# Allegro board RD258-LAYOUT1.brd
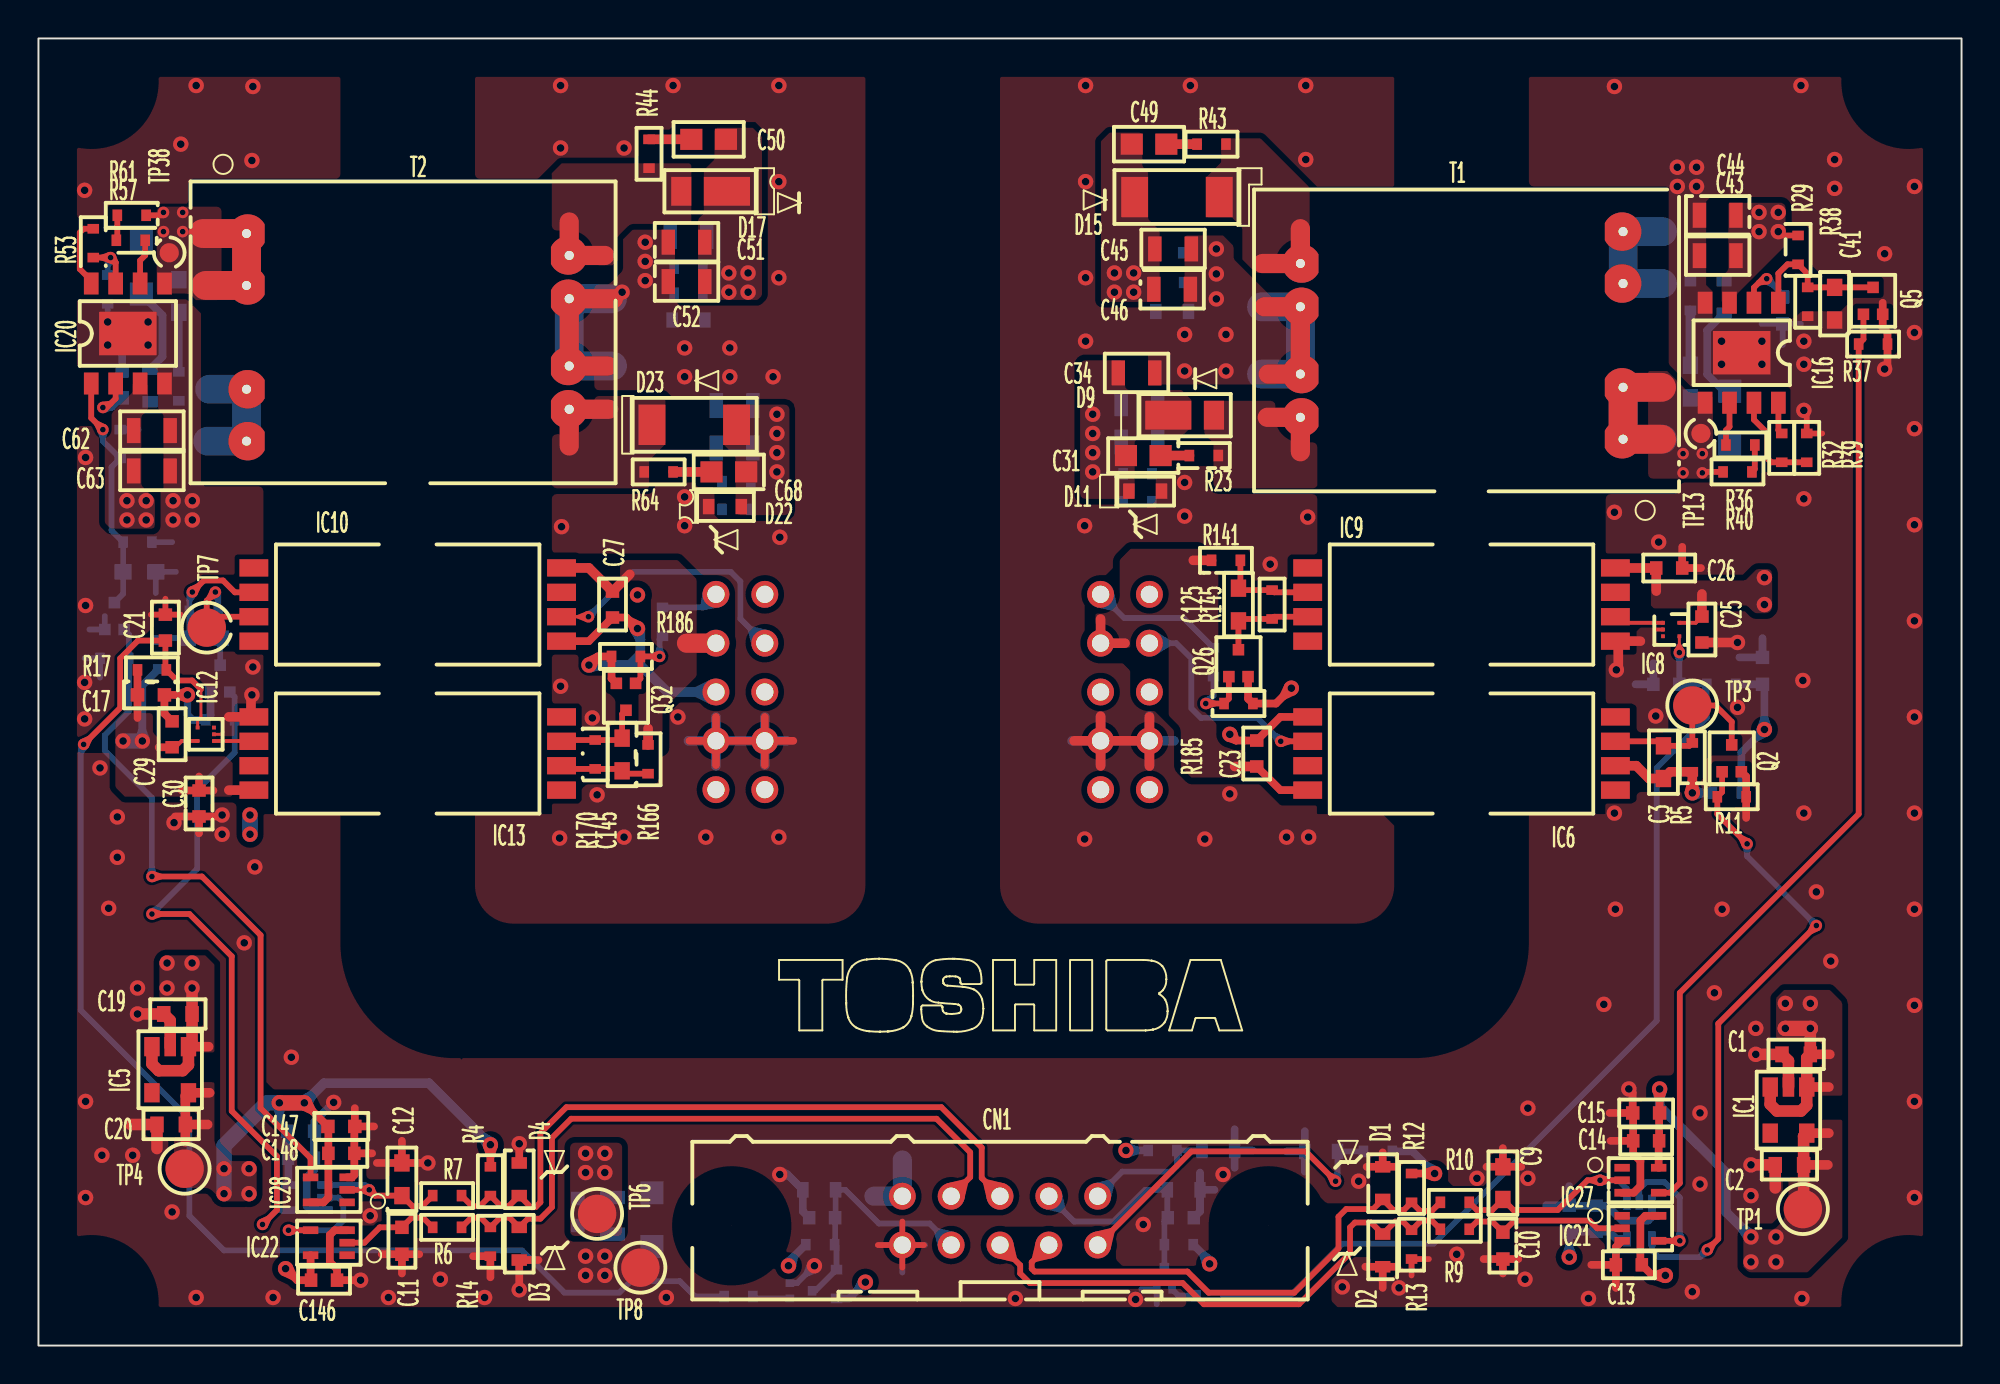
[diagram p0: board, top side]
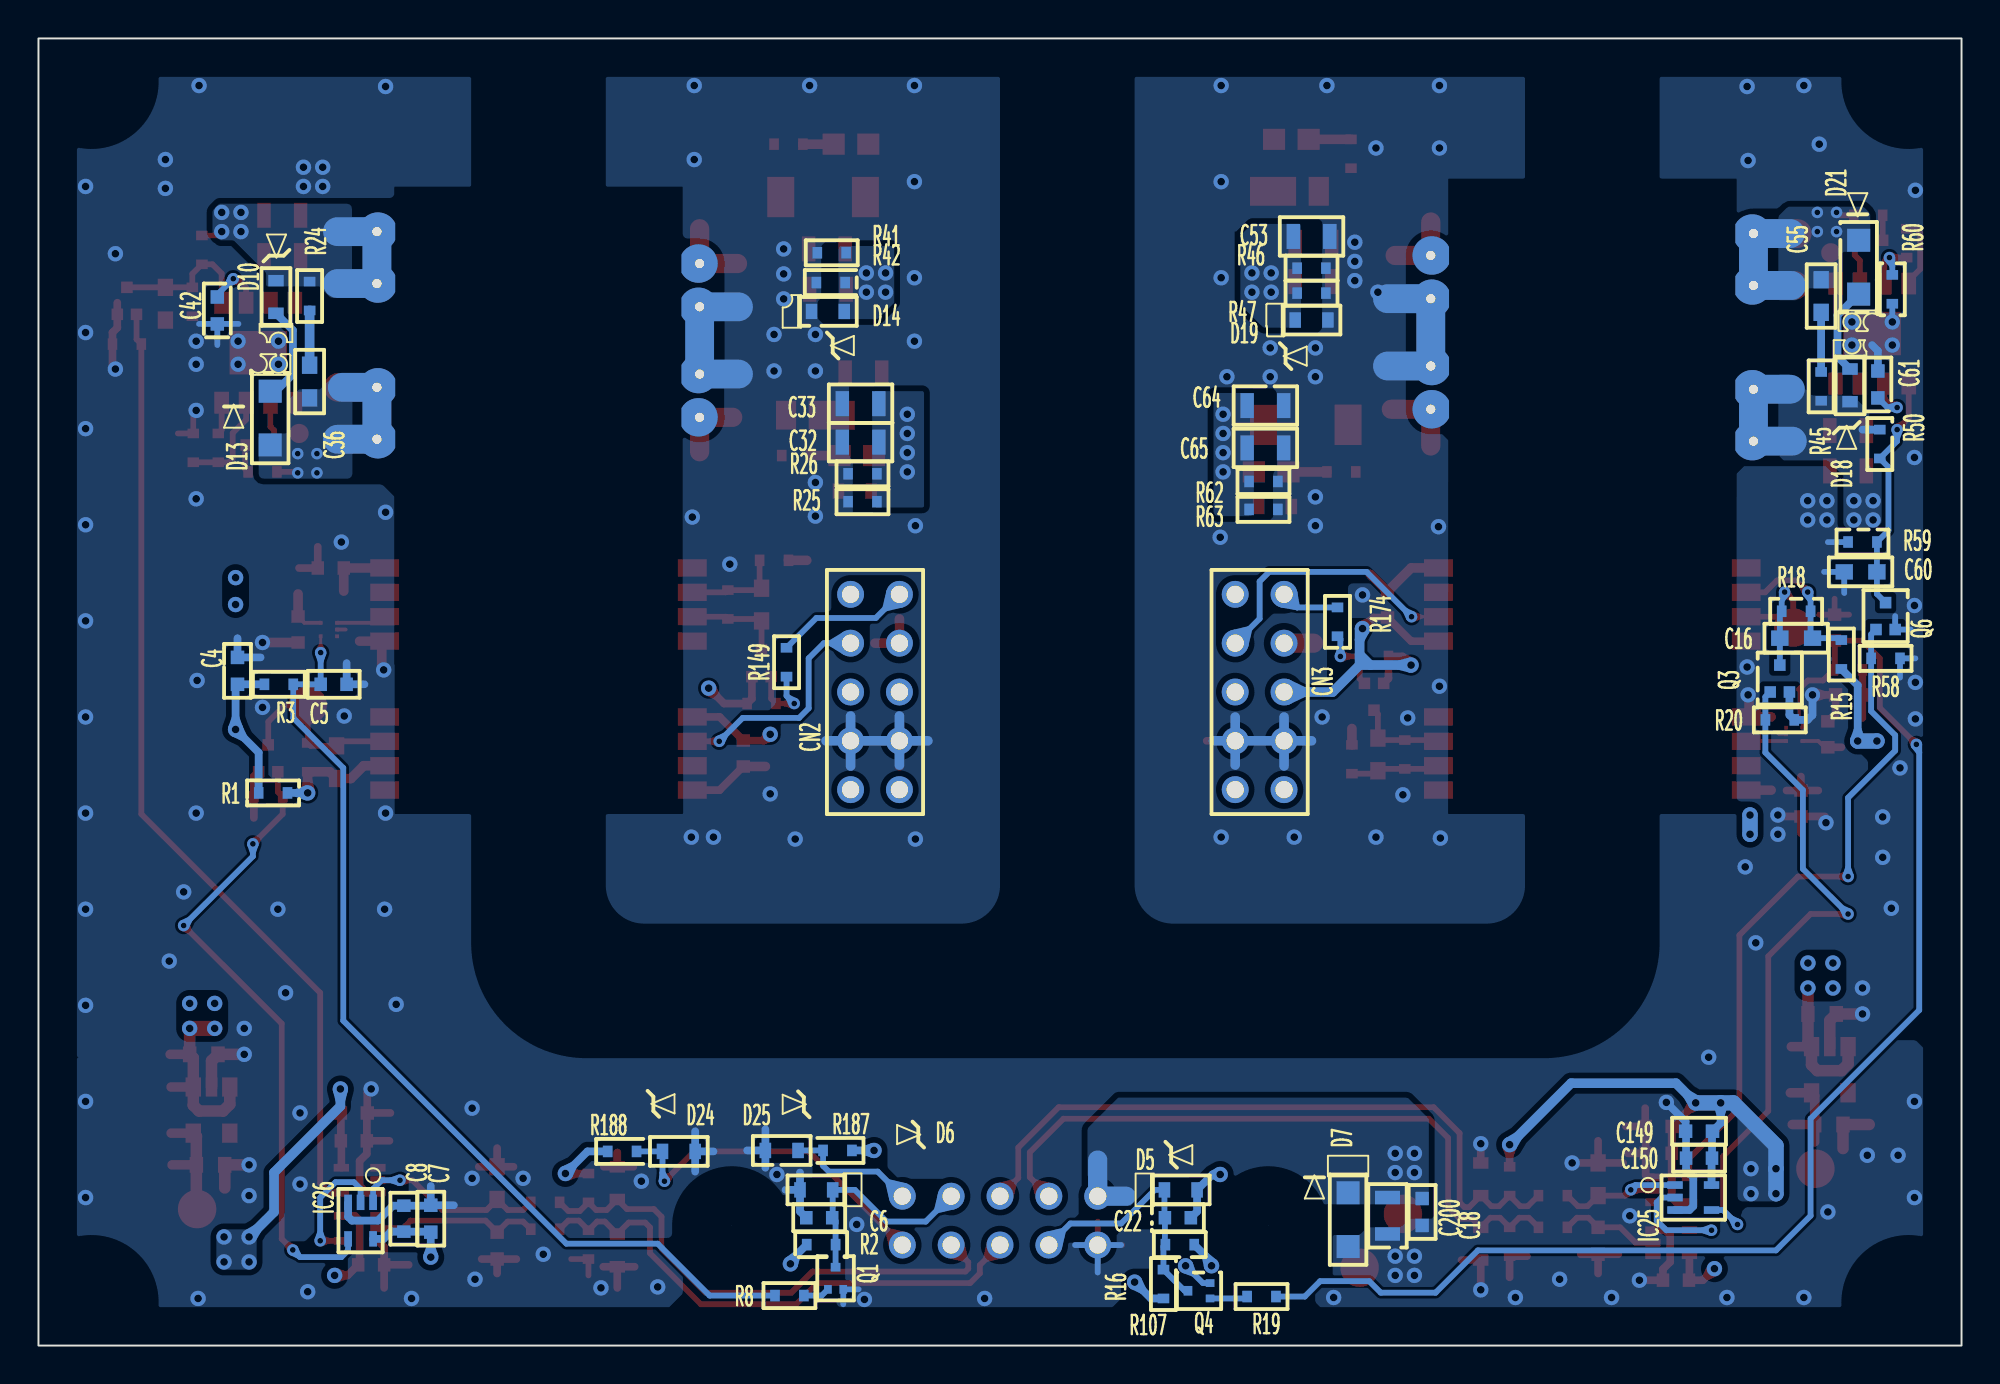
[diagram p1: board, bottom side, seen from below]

Outline 100 x 68 mm; copper layers: TOP, CONDUCTIVE2, CONDUCTIVE3, BOTTOM. Coordinates in mm from the lower left corner of the outline.
Outline path: rectangle 0,0 100,68

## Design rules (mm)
constraint set DEFAULT: 

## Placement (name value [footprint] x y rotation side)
C1  -  [C_CHP_TYYDN_L1_6W0_8H0_8A]  91.4 15.15 0 top
C2  -  [C_CHP_TYYDN_L1_6W0_8H0_8A]  91.05 9.4 0 top
C3  -  [C_CHP_YAGEO_L1_6W0_8H0_8]  84.5 30.35 270 top
C4  -  [C_CHP_TDK_L1_6W0_8H0_8]  89.65 35.1 270 bottom
C5  -  [C_CHP_MURATA_L1_6W0_8H0_8A]  84.65 34.4 0 bottom
C6  -  [C_CHP_MURATA_L1_6W0_8H0_8A]  59.4 6.65 180 bottom
C7  -  [C_CHP_TDK_L1_6W0_8H0_8]  79.6 6.6 270 bottom
C8  -  [C_CHP_MURATA_L1_6W0_8H0_8A]  81 6.6 270 bottom
C9  -  [C_CHP_YAGEO_L1_6W0_8H0_8]  76.15 8.45 270 top
C10  -  [C_CHP_TDK_L1_6W0_8H0_8]  76.15 5.2 90 top
C11  -  [C_CHP_TDK_L1_6W0_8H0_8]  18.9 5.45 90 top
C12  -  [C_CHP_YAGEO_L1_6W0_8H0_8]  18.9 8.65 270 top
C13  -  [C_CHP_MURATA_L1_6W0_8H0_8A]  82.7 4.2 0 top
C14  -  [C_CHP_MURATA_L1_6W0_8H0_8A]  83.6 10.65 0 top
C15  -  [C_CHP_TDK_L1_6W0_8H0_8]  83.6 12.1 0 top
C16  -  [C_CHP_YAGEO_L1_6W0_8H0_8]  8.6 36.8 180 bottom
C17  -  [C_CHP_TDK_L1_6W0_8H0_8]  5.85 33.85 180 top
C18  -  [C_CHP_TDK_L1_6W0_8H0_8]  28.05 6.95 90 bottom
C19  -  [C_CHP_TYYDN_L1_6W0_8H0_8A]  7.25 17.25 0 top
C20  -  [C_CHP_TYYDN_L1_6W0_8H0_8A]  6.9 11.5 0 top
C21  -  [C_CHP_MURATA_L1_6W0_8H0_8A]  6.6 37.35 270 top
C22  -  [C_CHP_MURATA_L1_6W0_8H0_8A]  40.75 6.65 0 bottom
C23  -  [C_CHP_MURATA_L1_6W0_8H0_8A]  63.35 30.8 270 top
C25  -  [C_CHP_MURATA_L1_6W0_8H0_8A]  86.5 37.25 90 top
C26  -  [C_CHP_MURATA_L1_6W0_8H0_8A]  84.8 40.45 180 top
C27  -  [C_CHP_MURATA_L1_6W0_8H0_8A]  29.85 38.55 90 top
C29  -  [C_CHP_MURATA_L1_6W0_8H0_8A]  6.95 31.8 270 top
C30  -  [C_CHP_MURATA_L1_6W0_8H0_8A]  8.35 28.2 90 top
C31  -  [C_CHP_KEMET_L1_6W0_8H0_8]  57.45 46.3 0 top
C32  -  [C_CHP_MURATA_L2_0W1_25H1_25]  57.25 47 180 bottom
C33  -  [C_CHP_MURATA_L2_0W1_25H1_25]  57.25 49 180 bottom
C34  -  [C_CHP_MURATA_L2_0W1_25H1_25]  57.1 50.6 180 top
C36  -  [C_CHP_YAGEO_L1_6W0_8H0_8]  85.9 50.15 90 bottom
C41  -  [C_CHP_YAGEO_L1_6W0_8H0_8]  93.4 54.2 90 top
C42  -  [C_CHP_TDK_L1_6W0_8H0_8]  90.7 53.85 90 bottom
C43  -  [C_CHP_MURATA_L2_0W1_25H1_25]  87.32 56.7 0 top
C44  -  [C_CHP_MURATA_L2_0W1_25H1_25]  87.32 58.8 0 top
C45  -  [C_CHP_MURATA_L2_0W1_25H1_25]  59 57.05 0 top
C46  -  [C_CHP_MURATA_L2_0W1_25H1_25]  58.95 54.95 0 top
C49  -  [C_CHP_KEMET_L1_6W0_8H0_8]  57.75 62.5 0 top
C50  -  [C_CHP_KEMET_L1_6W0_8H0_8]  34.85 62.75 180 top
C51  -  [C_CHP_MURATA_L2_0W1_25H1_25]  33.7 57.4 0 top
C52  -  [C_CHP_MURATA_L2_0W1_25H1_25]  33.7 55.35 0 top
C53  -  [C_CHP_MURATA_L2_0W1_25H1_25]  33.8 57.7 0 bottom
C55  -  [C_CHP_YAGEO_L1_6W0_8H0_8]  7.3 54.6 270 bottom
C60  -  [C_CHP_YAGEO_L1_6W0_8H0_8]  5.25 40.25 180 bottom
C61  -  [C_CHP_TDK_L1_6W0_8H0_8]  4.35 50 270 bottom
C62  -  [C_CHP_MURATA_L2_0W1_25H1_25]  5.9 47.6 180 top
C63  -  [C_CHP_MURATA_L2_0W1_25H1_25]  5.9 45.5 180 top
C64  -  [C_CHP_MURATA_L2_0W1_25H1_25]  36.2 48.9 180 bottom
C65  -  [C_CHP_MURATA_L2_0W1_25H1_25]  36.2 46.7 180 bottom
C68  -  [C_CHP_KEMET_L1_6W0_8H0_8]  35.9 45.45 180 top
C125  -  [C_CHP_YAGEO_L1_6W0_8H0_8]  62.4 38.55 90 top
C145  -  [C_CHP_YAGEO_L1_6W0_8H0_8]  30.35 30.75 270 top
C146  -  [C_CHP_MURATA_L1_6W0_8H0_8A]  14.85 3.4 0 top
C147  -  [C_CHP_TDK_L1_6W0_8H0_8]  15.75 11.4 180 top
C148  -  [C_CHP_MURATA_L1_6W0_8H0_8A]  15.75 10 180 top
C149  -  [C_CHP_TDK_L1_6W0_8H0_8]  13.65 11.15 180 bottom
C150  -  [C_CHP_MURATA_L1_6W0_8H0_8A]  13.65 9.75 180 bottom
C200  -  [C_CHP_MURATA_L2_0W1_25H1_25]  29.85 6.75 90 bottom
CN1  -  [CN_IMD_OMRON_XG4A_1031_M1_M2]  44.92 5.23 0 top
CN2  -  [OWW_3_15_5PW]  55.23 28.92 90 bottom
CN3  -  [OWW_3_15_5PW]  35.23 28.92 90 bottom
D1  -  [ZD_SMD_TSB_K_1_A_2_L1_2W0_8H0_6]  69.9 8.45 90 top
D2  -  [ZD_SMD_TSB_K_1_A_2_L1_2W0_8H0_6]  69.9 4.95 270 top
D3  -  [ZD_SMD_TSB_K_1_A_2_L1_2W0_8H0_6]  25 5.3 270 top
D4  -  [ZD_SMD_TSB_K_1_A_2_L1_2W0_8H0_6]  25 8.65 90 top
D5  -  [ZD_SMD_TSB_K_1_A_2_L1_2W0_8H0_6]  40.6 8.1 180 bottom
D6  -  [ZD_SMD_TSB_K_1_A_2_L1_2W0_8H0_6]  59.55 8.1 0 bottom
D7  -  [D_SMD_TSB_K_2_A_1_L2_6W1_6H0_98]  31.9 6.55 270 bottom
D9  -  [D_SMD_DIODES_K_C_A_A_L2_8W1_78H0_98]  59.6 48.4 0 top
D10  -  [ZD_SMD_TSB_K_1_A_2_L1_2W0_8H0_6]  87.65 54.55 90 bottom
D11  -  [ZD_SMD_TSB_K_1_A_2_L1_2W0_8H0_6]  57.55 44.45 0 top
D13  -  [D_SMD_TSB_K_2_A_1_L2_6W1_6H0_98]  87.95 48.25 270 bottom
D14  -  [ZD_SMD_TSB_K_1_A_2_L1_2W0_8H0_6]  58.95 53.8 180 bottom
D15  -  [D_SMD_TSB_K_2_A_1_L3_8W2_4H0_98]  59.2 59.75 180 top
D17  -  [D_SMD_DIODES_K_C_A_A_L2_8W1_78H0_98]  34.95 60.05 180 top
D18  -  [ZD_SMD_TSB_K_1_A_2_L1_2W0_8H0_6]  5.8 49.95 270 bottom
D19  -  [ZD_SMD_TSB_K_1_A_2_L1_2W0_8H0_6]  33.8 53.35 180 bottom
D21  -  [D_SMD_TSB_K_2_A_1_L2_6W1_6H0_98]  5.35 56.1 90 bottom
D22  -  [ZD_SMD_TSB_K_1_A_2_L1_2W0_8H0_6]  35.7 43.65 0 top
D23  -  [D_SMD_TSB_K_2_A_1_L3_8W2_4H0_98]  34.1 47.9 0 top
D24  -  [ZD_SMD_TSB_K_1_A_2_L1_2W0_8H0_6]  66.7 10.1 180 bottom
D25  -  [ZD_SMD_TSB_K_1_A_2_L1_2W0_8H0_6]  61.35 10.15 0 bottom
IC1  -  [IC_SC74A_TSB_L2_9W1_6H1_15_RP0_05]  91 12.25 180 top
IC5  -  [IC_SC74A_TSB_L2_9W1_6H1_15_RP0_05]  6.85 14.35 180 top
IC6  -  [PC_SOP_8_TSB_L6_25W13_75H3_7_P1_27_3]  74 30.8 90 top
IC8  -  [IC_SMD_5_TSB_L1_0W0_8H0_48_RCNT]  84.9 37.25 270 top
IC9  -  [PC_SOP_8_TSB_L6_25W13_75H3_7_P1_27_3]  74 38.55 270 top
IC10  -  [PC_SOP_8_TSB_L6_25W13_75H3_7_P1_27_3]  19.2 38.55 270 top
IC12  -  [IC_SMD_5_TSB_L1_0W0_8H0_48_RCNT]  8.7 31.8 90 top
IC13  -  [PC_SOP_8_TSB_L6_25W13_75H3_7_P1_27_3]  19.2 30.8 90 top
IC16  -  [IC_SOP_8S1_AD_L5_004W3_988H1_752_P1_27_2]  88.57 51.65 180 top
IC20  -  [IC_SOP_8S1_AD_L5_004W3_988H1_752_P1_27_2]  4.65 52.65 0 top
IC21  -  [IC_SOP_5_TSB_L2_0W1_25H0_95_RP0_05]  83.3 6.1 270 top
IC22  -  [IC_SOP_5_TSB_L2_0W1_25H0_95_RP0_05]  15.1 5.35 90 top
IC25  -  [IC_SOP_5_TSB_L2_0W1_25H0_95_RP0_05]  13.95 7.7 270 bottom
IC26  -  [IC_SOP_5_TSB_L2_0W1_25H0_95_RP0_05]  83.25 6.5 0 bottom
IC27  -  [IC_SOP_5_TSB_L2_0W1_25H0_95_RP0_05]  83.3 8.6 270 top
IC28  -  [IC_SOP_5_TSB_L2_0W1_25H0_95_RP0_05]  15.1 8.1 90 top
NOREF  -  []  38.5 16.4 0 top
Q1  -  [TR_SMD_3_TSB_B_1_E_2_C_3_L1_2W0_8H0_5]  58.55 3.5 180 bottom
Q2  -  [FET_SMD_TSB_G_1_S_2_D_3_L1_6W0_8H0_75]  88.05 30.55 0 top
Q3  -  [FET_SMD_TSB_G_1_S_2_D_3_L1_6W0_8H0_75]  9.45 34.7 180 bottom
Q4  -  [TR_SMD_3_TSB_B_1_E_2_C_3_L1_2W0_8H0_5]  39.65 2.85 90 bottom
Q5  -  [FET_SMD_TSB_G_1_S_2_D_3_L1_6W0_8H0_75]  95.4 54.35 0 top
Q6  -  [FET_SMD_TSB_G_1_S_2_D_3_L1_6W0_8H0_75]  3.95 37.95 180 bottom
Q26  -  [FET_SMD_TSB_G_1_S_2_D_3_L1_6W0_8H0_75]  62.4 35.5 0 top
Q32  -  [FET_SMD_TSB_G_1_S_2_D_3_L1_6W0_8H0_75]  30.55 33.75 180 top
R1  -  [R_CHP_KOA_L1_6W0_8H0_45]  87.8 28.75 0 bottom
R2  -  [R_CHP_KOA_L1_6W0_8H0_45]  59.3 5.25 0 bottom
R3  -  [R_CHP_KOA_L1_6W0_8H0_45]  87.5 34.4 0 bottom
R4  -  [R_CHP_KOA_L1_6W0_8H0_45]  23.5 8.55 90 top
R5  -  [R_CHP_KOA_L1_6W0_8H0_45]  86 30.6 270 top
R6  -  [R_CHP_KOA_L1_6W0_8H0_45]  21.25 6.15 180 top
R7  -  [R_CHP_KOA_L1_6W0_8H0_45]  21.25 7.8 180 top
R8  -  [R_CHP_KOA_L1_6W0_8H0_45]  60.95 2.6 0 bottom
R9  -  [R_CHP_KOA_L1_6W0_8H0_45]  73.65 6.05 0 top
R10  -  [R_CHP_KOA_L1_6W0_8H0_45]  73.65 7.45 0 top
R11  -  [R_CHP_KOA_L1_6W0_8H0_45]  88.05 28.55 180 top
R12  -  [R_CHP_KOA_L1_6W0_8H0_45]  71.4 8.2 90 top
R13  -  [R_CHP_KOA_L1_6W0_8H0_45]  71.4 5.25 90 top
R14  -  [R_CHP_KOA_L1_6W0_8H0_45]  23.5 5.4 90 top
R15  -  [R_CHP_KOA_L1_6W0_8H0_45]  6.25 35.95 270 bottom
R16  -  [R_CHP_KOA_L1_6W0_8H0_45]  40.65 5.25 180 bottom
R17  -  [R_CHP_KOA_L1_6W0_8H0_45]  5.9 35.15 180 top
R18  -  [R_CHP_KOA_L1_6W0_8H0_45]  8.6 38.2 180 bottom
R19  -  [R_CHP_KOA_L1_6W0_8H0_45]  36.4 2.55 180 bottom
R20  -  [R_CHP_KOA_L1_6W0_8H0_45]  9.45 32.55 0 bottom
R23  -  [R_CHP_KOA_L1_6W0_8H0_45]  60.6 46.3 0 top
R24  -  [R_CHP_KOA_L1_6W0_8H0_45]  85.9 54.6 90 bottom
R25  -  [R_CHP_KOA_L1_6W0_8H0_45]  57.15 43.9 180 bottom
R26  -  [R_CHP_KOA_L1_6W0_8H0_45]  57.15 45.35 180 bottom
R29  -  [R_CHP_KOA_L1_6W0_8H0_45]  91.5 57 90 top
R32  -  [R_CHP_KOA_L1_6W0_8H0_45]  90.65 46.7 90 top
R36  -  [R_CHP_KOA_L1_6W0_8H0_45]  88.5 46.85 180 top
R37  -  [R_CHP_KOA_L1_6W0_8H0_45]  95.4 52.1 180 top
R38  -  [R_CHP_KOA_L1_6W0_8H0_45]  92 54.3 90 top
R39  -  [R_CHP_KOA_L1_6W0_8H0_45]  91.95 46.7 270 top
R40  -  [R_CHP_KOA_L1_6W0_8H0_45]  88.35 45.45 0 top
R41  -  [R_CHP_KOA_L1_6W0_8H0_45]  58.75 56.85 0 bottom
R42  -  [R_CHP_KOA_L1_6W0_8H0_45]  58.8 55.3 0 bottom
R43  -  [R_CHP_KOA_L1_6W0_8H0_45]  61 62.5 0 top
R44  -  [R_CHP_KOA_L1_6W0_8H0_45]  31.75 62 270 top
R45  -  [R_CHP_KOA_L1_6W0_8H0_45]  7.3 49.9 270 bottom
R46  -  [R_CHP_KOA_L1_6W0_8H0_45]  33.8 56.05 0 bottom
R47  -  [R_CHP_KOA_L1_6W0_8H0_45]  33.8 54.75 0 bottom
R50  -  [R_CHP_KOA_L1_6W0_8H0_45]  4.25 46.9 90 bottom
R53  -  [R_CHP_KOA_L1_6W0_8H0_45]  2.85 57.35 90 top
R57  -  [R_CHP_KOA_L1_6W0_8H0_45]  4.8 57.5 0 top
R58  -  [R_CHP_KOA_L1_6W0_8H0_45]  3.95 35.75 0 bottom
R59  -  [R_CHP_KOA_L1_6W0_8H0_45]  5.15 41.8 180 bottom
R60  -  [R_CHP_KOA_L1_6W0_8H0_45]  3.6 54.95 90 bottom
R61  -  [R_CHP_KOA_L1_6W0_8H0_45]  4.85 58.8 180 top
R62  -  [R_CHP_KOA_L1_6W0_8H0_45]  36.3 44.95 180 bottom
R63  -  [R_CHP_KOA_L1_6W0_8H0_45]  36.3 43.5 180 bottom
R64  -  [R_CHP_KOA_L1_6W0_8H0_45]  32.25 45.45 180 top
R107  -  [R_CHP_KOA_L1_6W0_8H0_45]  41.5 3.2 270 bottom
R141  -  [R_CHP_KOA_L1_6W0_8H0_45]  61.75 40.85 180 top
R145  -  [R_CHP_KOA_L1_6W0_8H0_45]  64.15 38.55 90 top
R149  -  [R_CHP_KOA_L1_6W0_8H0_45]  61.1 35.55 270 bottom
R166  -  [R_CHP_KOA_L1_6W0_8H0_45]  31.7 30.5 90 top
R170  -  [R_CHP_KOA_L1_6W0_8H0_45]  28.95 30.75 270 top
R174  -  [R_CHP_KOA_L1_6W0_8H0_45]  32.45 37.65 270 bottom
R185  -  [R_CHP_KOA_L1_6W0_8H0_45]  62.4 33.4 180 top
R186  -  [R_CHP_KOA_L1_6W0_8H0_45]  30.55 35.85 0 top
R187  -  [R_CHP_KOA_L1_6W0_8H0_45]  58.45 10.15 180 bottom
R188  -  [R_CHP_KOA_L1_6W0_8H0_45]  69.65 10.1 180 bottom
T1  -  [750345989_2]  82.4 47.15 180 top
T2  -  [750345989_2]  10.82 57.85 0 top
TP1  -  [TPAD_P_C2_0_RP0_05_MN]  91.75 7.1 0 top
TP3  -  [TPAD_P_C2_0_RP0_05_MN]  86 33.3 270 top
TP4  -  [TPAD_P_C2_0_RP0_05_MN]  7.6 9.2 0 top
TP6  -  [TPAD_P_C2_0_RP0_05_MN]  29.05 6.85 0 top
TP7  -  [TPAD_P_C2_0_RP0_05_MN]  8.75 37.35 90 top
TP8  -  [TPAD_P_C2_0_RP0_05_MN]  31.3 4.05 0 top
TP13  -  [TPAD_P_C1_0_RP0_05_MN]  86.45 47.45 270 top
TP38  -  [TPAD_P_C1_0_RP0_05_MN]  6.8 56.85 90 top

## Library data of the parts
C1 C2 C19 C20 = MSASU168SB7474KTNB25
C3 C9 C12 C16 C36 C41 C55 C60 C125 C145 = CC0603KRX7R9BB471
C4 C17 = CGA3E3X7R1H334K080AB
C5 C6 C21 C22 = GCM188R71H102KA37D
C7 C15 C18 C42 C61 C147 C149 = C1608X5R1H105K080DB
C8 C13 C14 C23 C25-C27 C29 C30 C146 C148 C150 = GCJ188R71H104KA12D
C10 C11 = C1608X5R1H224K080AB
C31 C49 C50 C68 = C0603C470K1RACTU
C32-C34 C45 C46 C51-C53 C64 C65 C200 = GRM21BR61H106KE43L
C43 C44 C62 C63 = GRM21BZ71H475KE15L
CN1 = XG4A-1031_M1_M2: alternate symbols: (CN1_CN_IMD_OMRON_XG4A_1031_M1_M2)
CN2 CN3 = OWW-3-15-5PW: alternate symbols: (T:OWW_3_15_5PW;B:OWW_3_15_5PW,CN2_OWW_3_15_5PW,CN3_OWW_3_15_5PW)
D1-D6 D24 D25 = CEZ6V8,L3F
D7 = CRZ36(TE85L,Q,M)
D9 D17 = DFLS1100-7_Pin(K_C.A_A)
D10 D18 = CEZ24V,L3F
D11 D19 = CEZ30V,L3F
D13 D21 = CRS13
D14 D22 = CEZ8V2,L3F
D15 D23 = CMS03(T2L,TEMQ)
IC1 IC5 = TCR1HF50B,LM(CT
IC6 IC9 IC10 IC13 = TLP2861L
IC8 IC12 = TC7SZ04AFS,L3J
IC16 IC20 = LT8302IS8E#TRPBF
IC21 IC22 = TC7SZ17FU
IC25 IC26 = TC7SZ08FU
IC27 IC28 = TC7SZ14FU
Q1 Q4 = 2SC5658T2LR
Q2 Q3 Q5 Q6 Q26 Q32 = SSM3K15AFS,LF(T
R1 R15 = RK73H1JTTD5600F
R2 R4 R12-R14 R16 R107 = RK73H1JTTD4701F
R3 R11 R17 R20 R37 R39 R58 R60 = RK73H1JTTD1002F
R5-R7 R9 R10 R18 R145 R149 R170 R174 = RK73H1JTTD1001F
R8 R19 = RK73H1JTTD4702F
R23 R43 R44 R64 = RK73H1JTTD33R0F
R24 R45 = RK73H1JTTD39R0F
R25 R26 R41 R42 R46 R47 R62 R63 = RK73H1JTTD3001F
R29 R50 = RK73H1JTTD2403F
R32 R53 = RK73H1JTTD3903F
R36 R57 = RK73H1JTTD1003F
R38 R59 = RK73H1JTTD2202F
R40 R61 = RK73H1JTTD1602F
R141 R166 = RK73B1JTTD561J
R185 R186 = RK73B1JTTD104J
R187 R188 = RK73Z1JTTD
T1 T2 = 750345989: alternate symbols: (750345989_3)
TP1 TP3 TP4 TP6-TP8 = TPAD-P_C2.0-RP0.05-MN
TP13 TP38 = TPAD-P_C1.0-RP0.05-MN

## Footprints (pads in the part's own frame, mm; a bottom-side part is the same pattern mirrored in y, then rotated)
750345989_2
  custom 0.47x0.47 hole 1.2: 1(0,0) 2(0,-2.7) 4(0,-8.1) 5(0,-10.8)
  custom 0.475x0.475 hole 1.2: 12(16.78,-9.14) 13(16.78,-6.89) 14(16.78,-3.39) 15(16.78,-1.14)
C_CHP_KEMET_L1_6W0_8H0_8
  rect 1.15x1.1 smd: 1(-0.9,0) 2(0.9,0)
C_CHP_MURATA_L1_6W0_8H0_8A
  rect 0.65x0.7 smd: 1(-0.675,0) 2(0.675,0)
C_CHP_MURATA_L2_0W1_25H1_25
  rect 0.7x1.3 smd: 1(-0.95,0) 2(0.95,0)
C_CHP_TDK_L1_6W0_8H0_8
  rect 0.7x0.7 smd: 1(-0.7,0) 2(0.7,0)
C_CHP_TYYDN_L1_6W0_8H0_8A
  rect 0.7x0.825 smd: 1(-0.738,0) 2(0.738,0)
C_CHP_YAGEO_L1_6W0_8H0_8
  rect 0.9x0.8 smd: 1(-0.85,0) 2(0.85,0)
CN_IMD_OMRON_XG4A_1031_M1_M2
  round 0.01 hole 3.2 unplated: (-8.87,1) (19.03,1)
  round 1.4 hole 0.9: 1(0,0) 2(0,2.54) 3(2.54,0) 4(2.54,2.54) 5(5.08,0) 6(5.08,2.54) 7(7.62,0) 8(7.62,2.54) 9(10.16,0) 10(10.16,2.54)
D_SMD_DIODES_K_C_A_A_L2_8W1_78H0_98
  rect 1.05x1.5 smd: A(1.525,0)
  rect 2.4x1.5 smd: C(-0.85,0)
D_SMD_TSB_K_2_A_1_L2_6W1_6H0_98
  rect 1.2x1.2 smd: 1(1.4,0) 2(-1.4,0)
D_SMD_TSB_K_2_A_1_L3_8W2_4H0_98
  rect 1.4x2.1 smd: 1(2.2,0) 2(-2.2,0)
FET_SMD_TSB_G_1_S_2_D_3_L1_6W0_8H0_75
  rect 0.6x0.6 smd: 1(-0.5,-0.7) 2(0.5,-0.7) 3(0,0.7)
IC_SC74A_TSB_L2_9W1_6H1_15_RP0_05
  rect 0.8x1 smd: 1(-0.95,-1.2) 3(0.95,-1.2) 4(0.95,1.2) 5(-0.95,1.2)
  rect 0.6x1 smd: 2(0,-1.2)
IC_SMD_5_TSB_L1_0W0_8H0_48_RCNT
  rect 0.2x0.2 smd: 1(-0.35,-0.425) 2(0,-0.425) 3(0.35,-0.425) 4(0.35,0.425) 5(-0.35,0.425)
IC_SOP_5_TSB_L2_0W1_25H0_95_RP0_05
  rect 0.4x0.8 smd: 1(-0.65,-0.95) 2(0,-0.95) 3(0.65,-0.95) 4(0.65,0.95) 5(-0.65,0.95)
IC_SOP_8S1_AD_L5_004W3_988H1_752_P1_27_2
  rect 0.762x1.143 smd: 1(-1.905,-2.602) 2(-0.635,-2.602) 3(0.635,-2.602) 4(1.905,-2.602) 5(1.905,2.602) 6(0.635,2.602) 7(-0.635,2.602) 8(-1.905,2.602)
  rect 2.99x2.26 smd: 9(0,0)
OWW_3_15_5PW
  round 1.4 hole 0.9: 1(0,0) 2(0,2.54) 3(2.54,0) 4(2.54,2.54) 5(5.08,0) 6(5.08,2.54) 7(7.62,0) 8(7.62,2.54) 9(10.16,0) 10(10.16,2.54)
PC_SOP_8_TSB_L6_25W13_75H3_7_P1_27_3
  rect 0.9x1.5 smd: 1(-1.905,-8) 2(-0.635,-8) 3(0.635,-8) 4(1.905,-8) 5(1.905,8) 6(0.635,8) 7(-0.635,8) 8(-1.905,8)
R_CHP_KOA_L1_6W0_8H0_45
  rect 0.5x0.6 smd: 1(-0.75,0) 2(0.75,0)
TPAD_P_C1_0_RP0_05_MN
  round 1 smd: 1(0,0)
TPAD_P_C2_0_RP0_05_MN
  round 2 smd: 1(0,0)
TR_SMD_3_TSB_B_1_E_2_C_3_L1_2W0_8H0_5
  rect 0.4x0.45 smd: 1(-0.4,-0.575) 2(0.4,-0.575)
  rect 0.5x0.45 smd: 3(0,0.575)
ZD_SMD_TSB_K_1_A_2_L1_2W0_8H0_6
  rect 0.6x0.8 smd: 1(-0.85,0) 2(0.85,0)

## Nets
5V_A: C2.2 C4.2 C7.2 C8.2 C13.2 C14.2 C15.2 C25.2 C26.2 IC1.5 IC8.5 IC9.8 IC21.5 IC26.5 IC27.5 R1.2 R2.2 R3.2 R12.2 R107.2 R188.1 TP1.1
5V_B: C17.2 C20.2 C29.2 C30.2 C146.1 C147.2 C148.2 C149.2 C150.2 IC5.5 IC12.5 IC13.8 IC22.5 IC25.5 IC28.5 R4.2 R15.2 R16.2 R17.2 R187.2 TP4.1
GND: C1.1 C2.1 C4.1 C5.1 C6.1 C7.1 C8.1 C9.1 C10.1 C11.1 C12.1 C13.1 C14.1 C15.1 C17.1 C18.1 C19.1 C20.1 C21.1 C22.1 C25.1 C26.1 C29.1 C30.1 C41.1 C42.1 C43.1 C44.1 C60.1 C61.1 C62.1 C63.1 C146.2 C147.1 C148.1 C149.1 C150.1 C200.1 CN1.1 D1.2 D2.2 D3.2 D4.2 D5.2 D6.2 D7.1 D24.2 D25.2 IC1.2 IC5.2 IC8.2 IC9.5 IC12.2 IC13.5 IC16.4 IC16.9 IC20.4 IC20.9 IC21.3 IC22.3 IC25.3 IC26.3 IC27.3 IC28.3 Q1.2 Q2.2 Q3.2 Q4.2 Q5.2 Q6.2 R11.1 R13.1 R14.1 R20.1 R37.1 R38.1 R39.1 R58.1 R59.1 R60.1 TP8.1
VDD: C1.2 C18.2 C19.2 C43.2 C44.2 C62.2 C63.2 C200.2 CN1.2 D7.2 D10.2 D18.2 IC1.1 IC1.3 IC5.1 IC5.3 IC16.3 IC20.3 R24.2 R29.2 R45.2 R50.2 T1.4 T1.5 T2.4 T2.5 TP6.1
VEE_A: C23.1 C45.1 C46.1 C49.1 CN2.5 CN2.6 D14.2 D15.1 IC6.5 Q26.2 R41.1 R42.1 R185.1
VEE_B: C27.1 C64.1 C65.1 C68.1 CN3.5 CN3.6 D22.2 D23.1 IC10.5 Q32.2 R62.1 R63.1 R186.1
A_ENA: CN1.7 D1.1 R10.1 R12.1
A_FLT: C6.2 CN1.8 D6.1 Q1.3 R2.1
A_INA: CN1.5 D2.1 R9.1 R13.2
ANODE_A: C3.2 IC6.2 R1.1 R5.2
ANODE_B: C16.2 IC10.2 R15.1 R18.2
B_ENA: CN1.6 D4.1 R4.1 R7.1
B_FLT: C22.2 CN1.3 D5.1 Q4.3 R16.1 R107.1
B_INA: CN1.4 D3.1 R6.1 R14.2
CATHODE_A: C3.1 IC6.3 Q2.3 R5.1 TP3.1
CATHODE_B: C16.1 IC10.3 Q3.3 R18.1 TP7.1
FAULT_2_A: CN2.9 R149.1
FAULT_2_B: CN3.9 R174.1
FAULT_A: C5.2 IC8.4 R3.1 R8.2
FAULT_B: C21.2 IC12.4 R17.1 R19.2
FYB_DISABLE_A: IC27.4 Q5.1 R37.2
FYB_DISABLE_B: IC28.4 Q6.1 R58.2
IN2_N_A: CN2.8 IC6.6
IN2_N_B: CN3.8 IC10.6
SIG00001: Q1.1 R8.1
SIG00002: C9.2 IC26.1 IC27.2 R10.2
SIG00003: C10.2 IC21.2 R9.2
SIG00006: IC26.4 Q2.1 R11.2
SIG00007: IC25.4 Q3.1 R20.2
SIG00008: Q4.1 R19.1
SIG00011: CN1.9 D24.1 R188.2
SIG00013: CN1.10 D25.1 R187.1
SIG00027: IC8.1 IC9.6
SIG00032: IC12.1 IC13.6
SIG00040: D10.1 D13.2
SIG00041: C36.2 R24.1
SIG00042: D9.A R23.2 T1.15
SIG00043: C31.2 R23.1
SIG00044: C31.1 C32.2 C33.2 C34.2 CN2.1 CN2.2 D9.C D11.1 R25.2 R26.2
SIG00050: D15.2 R43.2 T1.12
SIG00051: C49.2 R43.1
SIG00052: C41.2 IC16.1 Q5.3 R29.1 R38.2
SIG00053: C42.2 IC16.2
SIG00054: IC16.7 R32.1 R39.2
SIG00055: IC16.8 R32.2
SIG00056: IC16.6 R36.2
SIG00057: R36.1 R40.2
SIG00058: C36.1 D13.1 IC16.5 R40.1 T1.1 T1.2 TP13.1
SIG00061: D18.1 D21.2
SIG00062: C55.2 R45.1
SIG00063: D17.A R44.2 T2.15
SIG00064: C50.2 R44.1
SIG00065: C50.1 C51.2 C52.2 C53.2 CN3.1 CN3.2 D17.C D19.1 R46.2 R47.2
SIG00071: D23.2 R64.2 T2.12
SIG00072: C68.2 R64.1
SIG00073: C60.2 IC20.1 Q6.3 R50.1 R59.2
SIG00074: C61.2 IC20.2
SIG00075: IC20.8 R53.2
SIG00076: IC20.7 R53.1 R60.2
SIG00077: IC20.6 R57.2
SIG00078: R57.1 R61.2
SIG00079: C55.1 D21.1 IC20.5 R61.1 T2.1 T2.2 TP38.1
SIG00190: Q26.1 R149.2 R185.2
SIG00227: Q32.1 R174.2 R186.2
SIG00237: C11.2 IC22.2 R6.2
SIG00240: IC21.4 IC26.2
SIG00241: IC22.4 IC25.2
SIG00242: C12.2 IC25.1 IC28.2 R7.2
VE_A: C32.1 C33.1 C34.1 C45.2 C46.2 CN2.3 CN2.4 D11.2 D14.1 R25.1 R26.1 R41.2 R42.2 T1.13 T1.14
VE_B: C51.1 C52.1 C53.1 C64.2 C65.2 CN3.3 CN3.4 D19.2 D22.1 R46.1 R47.1 R62.2 R63.2 T2.13 T2.14
VL_A: C23.2 CN2.7 IC6.8 R141.2
VL_B: C27.2 CN3.7 IC10.8 R166.2
N02405: C125.2 IC9.2 R141.1 R145.2
N76786: C125.1 IC9.3 Q26.3 R145.1
N938622: C145.2 IC13.2 R166.1 R170.2
N938626: C145.1 IC13.3 Q32.3 R170.1
N2071001: CN2.10
N2083572: IC6.4
N2083681: CN3.10
N2116820: IC5.4
N2119763: IC1.4
N2119767: IC6.1
N2119771: IC6.7
N2119775: IC9.1
N2119779: IC9.4
N2119783: IC9.7
N2119787: IC8.3
N2119802: IC10.1
N2119806: IC10.4
N2119810: IC13.7
N2119814: IC13.4
N2119818: IC13.1
N2119822: IC10.7
N2119826: IC12.3

Pads without a net: IC21 1; IC22 1; IC27 1; IC28 1

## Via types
v1: diameter 0.8, hole 0.4, TOP to BOTTOM, 242 vias
v2: diameter 0.6, hole 0.3, TOP to BOTTOM, 31 vias

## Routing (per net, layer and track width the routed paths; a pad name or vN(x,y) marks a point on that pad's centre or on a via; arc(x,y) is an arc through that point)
5V_A: length 81.1
  TOP w0.2: C25.2 86.17,37.6 IC8.5
  TOP w0.4: R12.2 v1(72.6,8.95) ; v1(84.6,3.65) 83.92,3.65 C13.2 83.3,4.28 83.3,6.5 83.55,6.75 IC21.5 ; v1(84.3,13.35) C15.2 84.28,12.07 84.28,10.65 84.25,10.62 IC27.5
  TOP w0.5: 84.12,39.25 C26.2 82.16,40.45 82.15,40.45 ; C25.2 86.5,39.1 ; IC1.5 93.1,11.05 ; C2.2 93.05,9.4
  TOP w0.6: IC1.5 91.79,10.89 C2.2 91.79,7.14 TP1.1
  CONDUCTIVE3 w0.6: 72.35,4.95 67.55,4.95 65.4,2.8 62.35,2.8 v1(60.9,4.25) 60.3,3.65 43.35,3.65 v1(43,3.3)
  BOTTOM w0.4: v1(60.9,4.25) 60.56,4.74 R2.2 ; v1(72.6,8.95) 71.45,10.1 R188.1 ; R107.2 42.15,2.45 v1(43,3.3) ; v1(79.6,4.6) C7.2 79.62,5.92 C8.2 81.67,5.92 82.05,5.55 IC26.5 ; R1.2 88.55,30.85 v1(89.75,32.05) 89.75,34.3 C4.2 R3.2
  BOTTOM w0.5: v1(89.05,5.65) 87.75,6.95 87.75,9 84.3,12.45 v1(84.3,13.35)
  vias: v1(89.05,4.35) v1(89.75,39.95) v1(89.75,38.55) v1(90.35,5.65) v1(90.35,4.35)
5V_B: length 105
  TOP w0.2: 8.28,31.45 7.45,31.45 7.12,31.12 C29.2
  TOP w0.4: R4.2 v1(23.5,10.45) ; R17.2 C17.2 5.15,32.65 ; v1(13.82,12.62) C147.2 15.07,11.38 C148.2 15.07,7.7 14.82,7.45 IC28.5 ; IC22.5 14.15,3.42 14.18,3.4 13.45,3.4 v1(12.85,4) ; C30.2 9.1,28.88 ; C30.2 8.35,29.6 ; C30.2 7.45,28.88 ; C29.2 6.25,31.12
  TOP w0.5: 11.05,28.89 9.9,28.89 ; C20.2 7.64,12.99 IC5.5 8.9,13.15 ; C20.2 8.8,11.5 ; C20.2 7.64,10.6
  TOP w0.8: v1(12.53,12.62) v1(13.82,12.62)
  CONDUCTIVE3 w0.6: 14,4.75 23.75,4.75 24.85,5.85 31.3,5.85 34.32,2.83 37.68,2.83 v1(39,4.15) 39.21,4.71 39.5,5 39.5,7.55 41.6,9.65 56.05,9.65 v1(56.55,10.15)
  BOTTOM w0.4: R16.2 39.31,4.66 v1(39,4.15) ; v1(5.4,31.45) 5.4,34.35 R15.2 ; IC25.5 13,9.72 C150.2 12.97,11.12 C149.2 12.53,11.57 v1(12.53,12.62) ; R187.2 v1(56.55,10.15)
  BOTTOM w0.5: v1(13.82,12.62) 14.85,13.65 20.3,13.65 v1(23.5,10.45)
  BOTTOM w0.8: v1(9.65,7.9) v1(9.65,9.2) 9.65,10.4 11.88,12.62 v1(12.53,12.62) v1(13.82,12.62) ; v1(4.4,31.45) v1(5.4,31.45)
  vias: v1(10.95,9.2) v1(10.95,7.9)
GND: length 152.5
  TOP w0.15: IC12.2 9.5,31.8 9.62,31.92
  TOP w0.2: 84.03,37.25 IC8.2
  TOP w0.3: 71.4,3.65 R13.1 72.3,4.5 ; C21.1 7.4,38.02 ; C21.1 6.6,38.85 ; C21.1 5.85,38.02 ; CN1.1 44.92,4.05 ; CN1.1 43.65,5.23 ; CN1.1 46.05,5.23 ; CN1.1 44.92,6.45 ; 91.95,48.5 R39.1 92.75,47.45
  TOP w0.4: IC28.3 16.3,8.75 16.43,8.88 C148.1 ; C13.1 82.03,3 ; C13.1 82.03,5.12 IC21.3 ; C13.1 80.75,4.2 ; Q2.2 88.8,29.6 R11.1 88.8,27.45 ; C148.1 17.35,10 ; C148.1 16.43,11.38 C147.1 ; IC22.3 15.4,6 15.15,5.75 15.15,4.35 15.53,3.98 C146.2 v1(16.75,3.4) ; C11.1 18.9,3.75 ; C11.1 17.85,4.75 ; C11.1 19.8,4.75 ; C9.1 75.3,9.3 ; C9.1 76.15,10.27 ; C9.1 77.1,9.3 ; 95.9,54.25 Q5.2 95.9,52.95 96.15,52.7 R37.1 96.15,50.95 v1(96,50.8) ; v1(25,2.9) D3.2 26,4.45 ; 23.5,3.55 R14.1 22.6,4.65 ; 85.47,41.55 C26.1 86.45,40.45 ; C30.1 8.35,26.65 ; C30.1 7.1,27.52 ; C30.1 9.5,27.52 ; C10.1 76.95,4.5 ; C10.1 76.15,3.75 ; C10.1 75.15,4.5 ; C15.1 82.9,13.15 v1(82.7,13.35) ; C15.1 81.7,12.1 ; C15.1 82.92,12.07 C14.1 ; D1.2 70.6,9.3 ; D1.2 69.07,9.3 ; D1.2 69.9,10.05 ; C12.1 v1(20.25,9.5) ; C12.1 18.9,10.65 ; C12.1 17.6,9.5 ; C14.1 82.92,9.97 83.3,9.6 83.3,8.3 82.95,7.95 IC27.3 ; C14.1 81.75,10.65 ; v1(7.75,33.85) C17.1 6.55,32.88 C29.1 ; 11,33.75 v1(11.1,33.85) ; D4.2 v1(25,10.5) ; D2.2 69,4.1 ; D2.2 70.63,4.1 ; D2.2 69.9,3 ; C147.1 17.45,11.4 ; C147.1 16.45,12.35
  TOP w0.5: 9.9,32.7 11.05,32.7 11.05,33.7 ; C25.1 v1(88.35,36.58) ; 83.3,36.65 82.15,36.65 82.15,35.3
  TOP w0.6: IC5.2 6.85,16.91 C19.1 v1(5.15,17.25) ; 90.31,8.2 C2.1 v1(89.05,9.4) ; 6.16,10.25 C20.1 4.8,11.5 ; v1(89.3,15.15) C1.1 91,14.81 IC1.2
  CONDUCTIVE2 w0.3: CN1.1 46.1,5.23 ; CN1.1 44.92,6.3 ; CN1.1 43.55,5.23 ; CN1.1 44.92,4.1
  CONDUCTIVE3 w0.3: CN1.1 46.2,5.23 ; CN1.1 44.92,6.3 ; CN1.1 43.5,5.23
  BOTTOM w0.3: CN1.1 44.92,3.8 ; CN1.1 46.1,5.23 ; CN1.1 43.7,5.23 ; 6.1,39.15 C60.1 7.15,40.25 ; C42.1 91.65,53.15 ; C42.1 90.7,52.05 ; C42.1 89.6,53.15 ; 3.2,34.75 R58.1 2.4,35.75 ; 2.65,37.25 Q6.2 3.45,37.95 ; 39.08,3.25 39.45,3.25 v1(40.35,4.15) ; 57.35,2.92 Q1.2 58.15,2.15 ; R59.1 6.95,41.8 ; R60.1 v1(3.6,53.25)
  BOTTOM w0.4: C7.1 79.62,7.28 81.58,7.28 82.35,6.5 83.7,6.5 83.9,6.7 IC26.3 ; C7.1 79.6,8.3 ; C7.1 78.4,7.3 ; v1(15.35,12.65) 14.35,11.65 C149.1 14.32,11.12 14.32,9.12 13.95,8.75 13.95,7.25 14.15,7.05 IC25.3 ; 89.65,36.8 C4.1 88.45,35.8 ; D24.2 64.9,10.1 ; D24.2 65.85,11.15 ; D24.2 65.85,9.05 ; D25.2 62.2,11.25 ; D25.2 63.15,10.15 ; D25.2 62.2,9.25 ; D6.2 60.4,9 ; D6.2 61.15,8.1 ; D6.2 60.4,6.97 60.08,6.65 ; C61.1 4.35,51.75 4.65,52.05 ; v1(7.75,33.85) 7.75,32.8 8,32.55 R20.1 8.95,32.8 Q3.2 ; 83.05,34.4 C5.1 83.97,35.5 ; C22.1 39.75,6.97 D5.2 38.95,8.9 v1(38.55,8.9)
  vias: v1(2.4,60.1) v1(2.4,34.5) v1(2.4,32.6) v1(2.45,46.2) v1(2.45,38.5) v1(2.45,12.7) v1(2.45,7.7) v1(3.2,30.05) v1(3.3,9.9) v1(3.6,52.05) v1(3.65,22.75) v1(4.1,27.5) v1(4.1,25.4) v1(4.9,9.9) v1(5.15,18.6) v1(5.7,53.25) v1(5.7,52.05) v1(7,43.95) v1(7,42.95) v1(7.05,27.2) v1(6.95,6.95) v1(7.4,62.5) v1(8,43.95) v1(8,42.95) v1(8.2,65.55) v1(8.2,2.5) v1(9.55,27.6) v1(9.55,26.6) v1(10.7,20.95) v1(11.1,61.65) v1(11.15,65.5) v1(11.15,35.3) v1(11.25,24.9) v1(12.2,2.5) v1(13.15,15) v1(17.25,6.75) v1(18.2,2.5) v1(20.9,3.45) v1(23.2,2.5) v1(28.45,4.65) v1(28.45,3.65) v1(29.45,4.65) v1(29.45,3.65) v1(32.65,2.5) v1(50.8,2.45) v1(57.05,2.4) v1(57.45,6.3) v1(61.6,8.9) v1(67.8,3.05) v1(68.65,8.55) v1(70.75,3) v1(73.75,4.75) v1(74.8,8.7) v1(77.3,3.45) v1(77.45,12.35) v1(77.45,8.7) v1(80.6,2.45) v1(81.4,17.75) v1(81.95,65.5) v1(81.95,43.35) v1(82.05,35.15) v1(81.95,27.7) v1(82,22.7) v1(84.1,32.75) v1(84.25,41.8) v1(85.22,61.3) v1(85.22,60.3) v1(86,2.8) v1(86.22,61.3) v1(86.22,60.3) v1(86.4,12.1) v1(86.4,8.4) v1(87.15,18.35) v1(87.52,52.25) v1(87.52,51.05) v1(87.55,22.7) v1(88.35,33.2) v1(89.05,7.8) v1(89.3,16.5) v1(89.62,52.25) v1(89.62,51.05) v1(91.65,65.55) v1(91.7,2.45) v1(91.8,52.25) v1(91.8,51.05) v1(91.8,48.65) v1(91.8,44.05) v1(91.75,34.6) v1(91.8,27.7) v1(92.45,23.6) v1(93.2,20) v1(93.4,61.7) v1(93.4,60.2) v1(96,56.8) v1(97.55,60.3) v1(97.55,52.7) v1(97.55,47.7) v1(97.55,42.7) v1(97.55,37.7) v1(97.55,32.7) v1(97.55,27.7) v1(97.55,22.7) v1(97.55,17.7) v1(97.55,12.7) v1(97.55,7.7)
VDD: length 38.5
  TOP w0.3: R29.2 90.47,57.75
  TOP w0.5: IC1.1 93.1,13.45 ; C1.2 93.15,15.15 ; IC5.1 8.85,15.55
  TOP w0.6: v1(7.99,18.6) C19.2 7.99,15.74 IC5.1 7.8,14.6 7.5,14.3 6.25,14.3 5.9,14.65 IC5.3 ; v1(92.14,16.5) C1.2 91.95,14.96 IC1.1 91.95,12.5 91.65,12.2 90.4,12.2 90.05,12.55 IC1.3
  TOP w0.8: v1(90.84,16.5) v1(92.14,16.5)
  BOTTOM w0.4: R50.2 5.15,47.65
  BOTTOM w0.8: v1(11,26.6) v1(11,27.6)
  BOTTOM w1: 43.45,7.77 CN1.2 44.92,9.65
  BOTTOM w1.5: 84.45,55.25 T1.4 T1.5 84.45,57.95 ; 8.9,49.75 T2.4 T2.5 8.8,47.05
  vias: v1(4.6,43.95) v1(4.6,42.95) v1(5.6,43.95) v1(5.6,42.95) v1(6.69,19.9) v1(6.69,18.6) v1(7.99,19.9) v1(28.45,10) v1(28.45,9) v1(29.45,10) v1(29.45,9) v1(89.47,58.95) v1(89.47,57.95) v1(90.47,58.95) v1(90.47,57.95) v1(90.84,17.8) v1(92.14,17.8)
VEE_A: length 17.6
  TOP w0.4: 65.9,32.7 64.58,32.7 C23.1 62.27,31.48 v1(61.95,31.8) ; v1(65.15,34.2) 64.35,33.4 R185.1 62.9,33.65 Q26.2
  CONDUCTIVE3 w0.5: CN2.6 58.85,32.92 ; CN2.6 56.77,33 ; CN2.6 56.57,35.2 ; CN2.6 58.8,35.03 ; 56.43,35.2 CN2.5 56.23,33
  vias: v1(55.95,55.8) v1(55.95,54.8) v1(56.95,55.8) v1(56.95,54.8)
VEE_B: length 24.3
  TOP w0.4: 27.35,36.65 28.62,36.65 C27.1 30.57,37.88 v1(31.15,37.3) ; Q32.2 29.8,34.7 R186.1 29.07,35.85 v1(28.62,35.4)
  CONDUCTIVE3 w0.5: CN3.6 37.77,35.25 ; CN3.6 CN3.5 34,35.23 ; CN3.6 39.2,34
  BOTTOM w0.5: CN3.5 32.7,34 31.3,35.4 ; v1(31.15,37.3) 31.3,36.72 31.3,35.95 ; 30.75,35.4 v1(28.62,35.4) ; 30.75,35.4 31.3,35.95 ; 30.75,35.4 31.3,35.4 ; 31.3,35.95 31.3,35.4
  vias: v1(38.4,48.45) v1(38.4,47.45) v1(38.4,46.45) v1(38.4,45.45)
A_ENA: length 27.1
  TOP w0.3: CN1.7 51.65,4.34 51.65,4 51.8,3.85 59.75,3.85 60.85,2.75 65.3,2.75 67.6,5.05 67.6,6.7 68,7.1 69.4,7.1 D1.1 70.45,7.05 71,7.05 R12.1 71.85,7 72.45,7 R10.1
A_FLT: length 11.5
  BOTTOM w0.3: CN1.8 53.86,6.45 55.9,6.45 57.55,8.1 D6.1 58.7,6.67 C6.2 58.55,6.47 R2.1 Q1.3
A_INA: length 28.1
  TOP w0.3: R9.1 72.45,6.5 71.9,6.5 R13.2 70.95,6.45 70.55,6.45 D2.1 69.3,6.4 68.45,6.4 68.2,6.15 68.2,4.8 65.55,2.15 60.6,2.15 59.5,3.25 51.55,3.25 51.05,3.75 51.05,4.18 CN1.5
ANODE_A: length 6.4
  TOP w0.5: v1(86,28.75) R5.2 84.85,29.85 C3.2 83.75,29.5 83.08,30.16 82.15,30.16
  BOTTOM w0.4: R1.1 v1(86,28.75)
ANODE_B: length 7.6
  TOP w0.3: v2(8,39.2) 8.6,39.8 9.6,39.8 10.21,39.19 11.05,39.19
  BOTTOM w0.3: v2(8,39.2) 7.85,38.78 R18.2 7.85,36.9 C16.2 6.35,36.8 R15.1
B_ENA: length 36.3
  TOP w0.3: R7.1 22.55,7.25 22.95,7.25 R4.1 24.05,7.25 24.45,7.25 D4.1 25.6,7.2 25.85,7.2 26.1,7.45 26.1,11.05 27.45,12.4 46.95,12.4 49.05,10.3 49.05,8.72 CN1.6
B_FLT: length 13.1
  BOTTOM w0.3: CN1.3 46.34,6.35 43.7,6.35 41.95,8.1 D5.1 41.45,6.67 C22.2 41.42,5.28 R16.1 41.5,5.15 R107.1 40.4,2.85 Q4.3
B_INA: length 35.1
  TOP w0.3: R6.1 22.5,6.65 23,6.65 R14.2 24,6.65 24.5,6.65 D3.1 25.45,6.6 26.1,6.6 26.7,7.2 26.7,10.8 27.7,11.8 46.7,11.8 48.45,10.05 48.45,8.76 CN1.4
CATHODE_A: length 9.6
  TOP w0.3: 82.15,31.43 84.27,31.43 C3.1 85.85,31.2 R5.1 TP3.1 87.2,33.3 88.05,32.45 Q2.3
CATHODE_B: length 8.4
  TOP w0.3: 11.05,37.91 9.31,37.91 TP7.1 8.75,38.75 v2(9.2,39.2)
  BOTTOM w0.3: Q3.3 C16.1 9.45,38.1 R18.1 9.35,38.78 v2(9.2,39.2)
FAULT_2_A: length 7
  BOTTOM w0.3: R149.1 59.55,37.85 56.46,37.85 CN2.9
FAULT_2_B: length 3.1
  BOTTOM w0.3: CN3.9 34.55,38.4 R174.1
FAULT_A: length 50.9
  TOP w0.15: IC8.4 v2(85.33,36.05)
  BOTTOM w0.3: R8.2 65.1,2.6 67.8,5.3 72.55,5.3 84.15,16.9 84.15,30.05 86.75,32.65 R3.1 C5.2 v2(85.33,36.05)
FAULT_B: length 70.7
  TOP w0.15: 8.45,34.14 8.45,32.7 8.28,32.52 8.28,32.15
  TOP w0.3: v2(2.35,31.27) 4.25,33.17 4.25,35.75 5.17,36.67 C21.2 6.6,35.2 R17.1 7.2,34.6 7.99,34.6 8.45,34.14
  BOTTOM w0.3: v2(2.35,31.27) 2.2,30.85 2.2,17.45 7.85,11.8 7.85,6.75 9.65,4.95 25.15,4.95 27.35,2.75 30.2,2.75 30.8,3.35 33.35,3.35 34.15,2.55 R19.2
FYB_DISABLE_A: length 50.5
  TOP w0.3: Q5.1 94.9,52.35 R37.2 94.65,27.65 85.35,18.35 85.35,8.45 84.85,7.95 IC27.4
FYB_DISABLE_B: length 35.1
  TOP w0.3: v2(5.9,24.4) 8.5,24.4 11.55,21.35 11.55,12.35 14.15,9.75 IC28.4
  BOTTOM w0.3: Q6.1 4.7,37 R58.2 4.7,33 3.45,31.75 3.45,30.95 5.9,28.5 v2(5.9,24.4)
IN2_N_A: length 11.8
  TOP w0.3: 65.9,31.43 v2(64.6,31.43)
  BOTTOM w0.3: CN2.8 59.16,36.54 59.95,35.75 59.95,33.15 60.45,32.65 63.38,32.65 v2(64.6,31.43)
IN2_N_B: length 14.1
  TOP w0.15: v2(28.6,37.91) 27.35,37.91
  BOTTOM w0.3: v2(28.6,37.91) 30.93,40.25 36,40.25 36.5,39.75 36.5,37.81 CN3.8
SIG00001: length 1.4
  BOTTOM w0.3: R8.1 59.27,2.6 Q1.1
SIG00002: length 11.5
  TOP w0.3: R10.2 74.8,7.05 75.6,7.05 C9.2 76.7,7.05 79,7.05 80.55,8.6 v2(81.2,8.6) IC27.2
  BOTTOM w0.3: v2(81.2,8.6) 82.15,8.6 82.6,8.15 IC26.1
SIG00003: length 8.8
  TOP w0.3: IC21.2 81.05,6.1 80.65,6.5 76.75,6.5 C10.2 75.6,6.45 74.8,6.45 R9.2
SIG00006: length 33.2
  TOP w0.3: Q2.1 87.55,28.8 R11.2 87.3,27.65 v2(88.85,26.1) ; v2(92.45,21.85) 87.35,16.75 87.35,5.55 v2(86.78,4.97)
  BOTTOM w0.3: v2(92.45,21.85) 88.85,25.45 v2(88.85,26.1) ; v2(86.78,4.97) 86.4,4.6 84.25,4.6 83.9,4.95 IC26.4
SIG00007: length 35.4
  TOP w0.3: v2(11.65,6.3) 12.4,7.05 12.4,9.85 10.05,12.2 10.05,20.25 7.85,22.45 v2(5.9,22.45)
  BOTTOM w0.3: v2(11.65,6.3) 12.4,7.05 IC25.4 ; v2(5.9,22.45) 8.25,24.8 8.25,28.9 10.2,30.85 R20.2 10.2,33.75 Q3.1
SIG00008: length 2
  BOTTOM w0.3: 39.08,2.45 37.25,2.45 R19.1
SIG00011: length 17.9
  TOP w0.3: v2(67.45,8.55) 65.9,10.1 59.95,10.1 CN1.9
  BOTTOM w0.3: v2(67.45,8.55) 67.55,8.99 D24.1 R188.2
SIG00013: length 6.9
  BOTTOM w0.3: D25.1 R187.1 59.2,9.35 58.9,9.05 56.36,9.05 CN1.10
SIG00027: length 2.5
  TOP w0.2: IC8.1 82.47,37.6 82.15,37.91
SIG00032: length 1.9
  TOP w0.2: IC12.1 11.04,31.45 11.05,31.43
SIG00040: length 5.1
  BOTTOM w0.4: D10.1 86.77,52.82 86.77,50.53 87.65,49.65 D13.2
SIG00041: length 2.9
  BOTTOM w0.5: R24.1 C36.2
SIG00042: length 3.5
  TOP w1: 63.9,48.29 T1.15 65.62,46.5
SIG00043: length 1.5
  TOP w0.5: R23.1 C31.2
SIG00044: length 10.7
  CONDUCTIVE3 w0.5: CN2.1 55.23,30.2 ; CN2.1 53.45,28.92 ; CN2.1 CN2.2 ; CN2.1 55.23,27.68 ; CN2.2 57.77,27.68 ; CN2.2 57.77,30.15 ; CN2.2 59.2,28.92
  vias: v1(54.82,48.45) v1(54.82,47.45) v1(54.82,46.45) v1(54.82,45.45)
SIG00050: length 3.8
  TOP w1: 63.65,56.29 T1.12 65.62,58.1
SIG00051: length 1.6
  TOP w0.5: R43.1 C49.2
SIG00052: length 7.6
  TOP w0.3: IC16.1 90.47,55.77 90.95,56.25 R29.1 92,55.75 R38.2 C41.2 Q5.3
SIG00053: length 2.9
  TOP w0.3: v2(89.87,55.5) 89.47,55.3 89.2,55.03 IC16.2
  BOTTOM w0.3: v2(89.87,55.5) 90.7,54.67 C42.2
SIG00054: length 5.3
  TOP w0.3: IC16.7 89.2,48.16 89.9,47.47 89.9,46.15 90.1,45.95 R32.1 R39.2
SIG00055: length 1.7
  TOP w0.3: R32.2 90.47,47.62 IC16.8
SIG00056: length 2.3
  TOP w0.3: 87.94,49.05 87.94,47.8 87.75,47.62 R36.2
SIG00057: length 1.5
  TOP w0.3: R40.2 89.25,45.6 R36.1
SIG00058: length 14.3
  TOP w0.3: R40.1 86.57,45.45
  TOP w1.5: 84.4,49.85 T1.2 T1.1 84.4,47.15
  BOTTOM w1.5: 84.45,47.15 T1.1 T1.2 84.2,49.85
  vias: v2(85.52,46.4) v2(85.52,45.4) v2(86.52,46.4) v2(86.52,45.4)
SIG00061: length 4.6
  BOTTOM w0.4: D18.1 6.45,51.45 6.45,53.6 D21.2
SIG00062: length 3.1
  BOTTOM w0.4: R45.1 C55.2
SIG00063: length 3.6
  TOP w1: 29.45,56.71 T2.15 27.6,58.45
SIG00064: length 2.2
  TOP w0.5: R44.1 C50.2
SIG00065: length 10.5
  CONDUCTIVE3 w0.5: CN3.2 37.77,27.63 ; CN3.2 37.77,30.1 ; CN3.2 39.15,28.92 ; CN3.2 CN3.1 ; CN3.1 33.6,28.92 ; CN3.1 35.23,27.63 ; CN3.1 35.23,30.1
  vias: v1(35.9,55.8) v1(35.9,54.8) v1(36.9,55.8) v1(36.9,54.8)
SIG00071: length 4
  TOP w1: 29.65,48.71 T2.12 27.6,46.8
SIG00072: length 2
  TOP w0.5: R64.1 C68.2
SIG00073: length 12.6
  TOP w0.3: IC20.1 2.75,48.26 v2(3.35,47.65)
  BOTTOM w0.3: v2(3.35,47.65) 3.35,47.05 R50.1 3.8,45.7 3.8,42.4 R59.2 C60.2 4.4,39.1 Q6.3
SIG00074: length 2.8
  TOP w0.3: 4.01,50.05 4.01,49.27 3.75,49 v2(3.35,48.8)
  BOTTOM w0.3: C61.2 3.85,48.8 v2(3.35,48.8)
SIG00075: length 3.7
  TOP w0.3: IC20.8 2.75,55.41 2.15,56 2.15,57.9 2.35,58.1 R53.2
SIG00076: length 3.3
  TOP w0.3: 4.01,55.25 4.01,56.34 v2(3.75,56.6) R53.1
  BOTTOM w0.3: v2(3.75,56.6) 3.6,56.18 R60.2
SIG00077: length 2.4
  TOP w0.3: IC20.6 5.29,56.45 5.55,56.72 R57.2
SIG00078: length 1.3
  TOP w0.3: R57.1 4.1,57.55 R61.2
SIG00079: length 14.6
  TOP w0.3: R61.1 6.5,58.8
  TOP w1.5: 8.7,55.15 T2.2 T2.1 8.55,57.85
  BOTTOM w1.5: 8.9,57.85 T2.1 T2.2 8.85,55.15
  vias: v2(6.5,58.95) v2(6.5,57.95) v2(7.5,58.95) v2(7.5,57.95)
SIG00190: length 4
  TOP w0.3: Q26.1 61.9,33.65 R185.2 v2(60.7,33.4)
  BOTTOM w0.3: v2(60.7,33.4) 61.1,33.8 R149.2
SIG00227: length 3.6
  TOP w0.3: v2(32.3,35.85) R186.2 31.3,34.7 Q32.1
  BOTTOM w0.3: R174.2 32.3,36.75 v2(32.3,35.85)
SIG00237: length 5.2
  TOP w0.3: IC22.2 16.95,5.35 17.75,6.15 C11.2 19.4,6.65 20,6.65 R6.2
SIG00240: length 6.6
  TOP w0.3: IC21.4 v2(85.35,5.45)
  BOTTOM w0.3: v2(85.35,5.45) 85.35,7.7 84.55,8.5 83.6,8.5 83.25,8.15 IC26.2
SIG00241: length 6.2
  TOP w0.3: IC22.4 v2(13,6)
  BOTTOM w0.3: IC25.2 15.6,7.7 15.85,7.45 15.85,6.5 15.35,6 v2(13,6)
SIG00242: length 7.4
  TOP w0.3: IC28.2 v2(17.2,8.1) 17.5,7.8 C12.2 19.45,7.25 19.95,7.25 R7.2
  BOTTOM w0.3: v2(17.2,8.1) 16.95,8.35 IC25.1
VE_A: length 62.9
  TOP w0.5: CN2.3 CN2.4 ; CN2.3 55.23,30.15 ; CN2.3 55.23,32.74 ; CN2.3 53.85,31.46 ; CN2.4 57.77,32.71 ; CN2.4 57.77,30.15
  TOP w1: 63.75,54.04 T1.13 T1.14 63.95,50.54
  CONDUCTIVE2 w0.3: 63.8,50.54 T1.14 T1.13 63.8,54.04
  CONDUCTIVE2 w0.5: CN2.4 57.77,32.75 ; CN2.4 CN2.3 ; CN2.4 57.77,30.2 ; CN2.4 59.4,31.46 ; CN2.3 55.23,30.2 ; CN2.3 53.8,31.46 ; CN2.3 55.23,32.75
  CONDUCTIVE3 w0.3: 64.05,54.04 T1.13 T1.14 63.9,50.54
  CONDUCTIVE3 w0.5: 59.45,31.46 CN2.4 CN2.3
  BOTTOM w0.5: CN2.3 55.23,32.75 ; CN2.3 53.75,31.46 ; CN2.3 55.23,30.2 ; CN2.3 CN2.4 ; CN2.4 57.77,30.15 ; CN2.4 59.05,31.46 ; CN2.4 57.77,32.75
  BOTTOM w1.5: 63.6,50.54 T1.14 T1.13 63.6,54.04
  vias: v1(54.4,42.65) v1(54.4,26.35) v1(54.45,65.55) v1(54.45,60.55) v1(54.45,55.55) v1(54.45,52.25) v1(59.6,52.6) v1(59.6,50.7) v1(59.6,44.9) v1(59.6,43.15) v1(59.9,65.55) v1(60.65,26.35) v1(61.25,57.05) v1(61.25,55.75) v1(61.25,54.45) v1(61.75,52.6) v1(61.75,50.7) v1(61.95,28.7) v1(64.05,40.65) v1(64.9,26.45) v1(65.9,65.55) v1(65.9,61.7) v1(66,43.1) v1(66.05,26.45)
VE_B: length 66.5
  TOP w0.4: CN3.4 CN3.3 ; CN3.4 39.25,31.46 ; CN3.4 37.77,32.7 ; CN3.4 37.77,30.2 ; CN3.3 33.85,31.46 ; CN3.3 35.23,32.7 ; CN3.3 35.23,30.2
  TOP w1: 29.9,54.46 T2.14 T2.13 29.6,50.96
  CONDUCTIVE2 w0.3: 29.1,50.96 T2.13 T2.14 29.1,54.46
  CONDUCTIVE2 w0.5: CN3.3 35.23,30.2 ; CN3.3 33.75,31.46 ; CN3.3 CN3.4 ; CN3.3 35.23,32.7 ; CN3.4 37.77,32.75 ; CN3.4 37.77,30.2 ; CN3.4 39.2,31.46
  CONDUCTIVE3 w0.3: 29.2,50.96 T2.13 T2.14 29.35,54.46
  CONDUCTIVE3 w0.5: CN3.3 33.75,31.46 ; CN3.3 35.23,32.64 ; CN3.3 CN3.4 37.77,32.53
  BOTTOM w0.5: CN3.3 CN3.4 ; CN3.3 33.8,31.46 ; CN3.3 35.23,30.15 ; CN3.3 35.23,32.7 ; CN3.4 37.77,32.7 ; CN3.4 37.77,30.2 ; CN3.4 38.9,31.46
  BOTTOM w1.5: 29.85,50.96 T2.13 T2.14 29.85,54.46
  vias: v1(27.15,65.55) v1(27.15,62.3) v1(27.15,34.3) v1(27.1,26.4) v1(27.2,42.6) v1(28.8,32.65) v1(29.05,28.65) v1(30.45,62.3) v1(30.35,54.8) v1(30.45,26.45) v1(31.15,39.05) v1(31.55,57.4) v1(31.55,56.4) v1(31.55,55.4) v1(33,65.55) v1(33.25,32.7) v1(33.6,51.9) v1(33.6,50.4) v1(33.6,44.15) v1(33.6,42.65) v1(34.7,26.45) v1(35.95,51.9) v1(35.95,50.4) v1(38.2,50.4) v1(38.5,65.55) v1(38.5,60.55) v1(38.5,55.55) v1(38.55,42.05) v1(38.5,26.45)
VL_A: length 7.7
  TOP w0.4: C23.2 64.58,28.89 65.9,28.89
  TOP w0.5: C23.2 62.2,30.12 ; 56.5,36.54 CN2.7 55.23,37.8 ; R141.2 60.05,40.85
VL_B: length 6.7
  TOP w0.5: R166.2 31.7,32.1 ; 27.35,40.45 28.62,40.45 C27.2 30.75,40.12
  TOP w1: CN3.7 33.7,36.54
N02405: length 5.1
  TOP w0.3: 65.9,39.19 64.27,39.19 R145.2 62.5,39.3 C125.2 62.5,39.5 R141.1
N76786: length 5.1
  TOP w0.3: 65.9,37.91 64.27,37.91 R145.1 62.5,37.8 C125.1 Q26.3
N938622: length 4.5
  TOP w0.3: R166.1 30.5,29.75 C145.2 30.25,30 R170.2 27.52,30 27.35,30.16
N938626: length 4.6
  TOP w0.3: 27.35,31.43 27.41,31.5 R170.1 30.25,31.5 C145.1 30.35,32.85 Q32.3

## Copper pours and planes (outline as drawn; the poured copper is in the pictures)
5V_A on TOP: 89.04,3.81 88.98,3.82 88.86,3.89 88.68,4.07 88.66,4.1 88.65,4.14 88.65,5.65 88.77,5.93 89.05,6.05 90.11,6.05 90.26,6.08 90.39,6.17 90.68,6.45 90.78,6.63 90.78,6.84 90.76,7.26 90.92,7.65 90.98,7.78 91,7.9 91,8.64 91.03,8.71 91.1,8.74 92.19,8.74 92.29,8.76 92.36,8.84 92.39,8.94 92.39,9.86 92.36,9.96 92.29,10.04 92.19,10.06 91.6,10.06 91.53,10.09 91.5,10.16 91.5,10.2 91.53,10.27 91.6,10.3 92.3,10.3 92.51,10.39 92.6,10.6 92.6,11.5 92.59,11.56 92.57,11.65 92.6,11.72 92.67,11.75 93.7,11.75 93.77,11.72 93.8,11.65 93.8,5.67 93.79,5.63 93.77,5.59 92.02,3.84 91.98,3.82 91.95,3.81
5V_A on TOP: 88.92,38.43 88.81,38.49 88.75,38.5 86.1,38.5 86,38.47 85.89,38.36 85.84,38.35 84.04,38.35 84,38.36 83.97,38.38 83.88,38.47 83.86,38.5 83.85,38.54 83.85,39.75 83.88,39.82 83.95,39.85 84.99,39.85 85.02,39.85 85.12,39.81 85.2,39.8 88.65,39.8 88.77,39.83 88.82,39.87 89.28,40.33 89.33,40.37 89.45,40.4 89.9,40.4 90.03,40.37 90.12,40.27 90.15,40.15 90.15,38.4 90.14,38.34 90.08,38.23 90.02,38.17 89.97,38.13 89.85,38.1 89.35,38.1 89.29,38.11 89.18,38.17
5V_A on BOTTOM: 89.05,3.95 88.77,4.07 88.65,4.35 88.65,5.53 88.62,5.68 88.53,5.81 87.57,6.77 87.52,6.85 87.5,6.95 87.5,7.19 87.52,7.25 87.57,7.29 87.61,7.3 87.65,7.3 87.9,7.3 87.97,7.27 88,7.2 88.03,7.06 88.12,6.94 88.89,6.17 89.02,6.08 89.17,6.05 90.35,6.05 90.63,5.93 90.75,5.65 90.75,4.35 90.63,4.07 90.35,3.95
5V_A on CONDUCTIVE3: outline of 118 points within 72,3.2 96.65,40.35 ; 5 cut-outs
5V_B on TOP: 4.54,28.55 4.5,28.56 4.47,28.58 4.04,29.01 4,29.11 4,30.65 4,32.35 4.01,32.41 4.07,32.52 4.42,32.87 4.45,32.89 4.49,32.9 5.8,32.9 5.91,32.86 5.95,32.75 5.95,31.95 5.99,31.84 6.32,31.52 6.34,31.48 6.35,31.45 6.35,30.75 6.38,30.65 6.45,30.58 6.55,30.55 7.35,30.55 7.43,30.57 7.53,30.64 7.57,30.65 9.69,30.65 9.79,30.61 10.07,30.33 10.09,30.3 10.1,30.26 10.1,28.7 10.06,28.59 9.95,28.55 9.05,28.55 8.98,28.58 8.95,28.65 8.95,29.25 8.92,29.35 8.85,29.42 8.75,29.45 7.95,29.45 7.85,29.42 7.78,29.35 7.75,29.25 7.75,28.65 7.72,28.58 7.65,28.55
5V_B on TOP: 9.65,7.5 9.42,7.57 9.27,7.76 9.24,7.84 9.18,7.91 9.05,8.04 8.87,8.16 8.66,8.2 7.6,8.2 7.34,8.23 7.1,8.33 7.06,8.37 7.05,8.42 7.05,10.75 7.09,10.83 7.18,10.85 7.21,10.84 7.24,10.84 8.04,10.84 8.18,10.9 8.24,11.04 8.24,11.96 8.18,12.1 8.04,12.16 7.55,12.16 7.48,12.19 7.45,12.26 7.45,12.3 7.48,12.37 7.55,12.4 8.15,12.4 8.36,12.49 8.45,12.7 8.45,13.6 8.48,13.67 8.55,13.7 9.05,13.7 9.12,13.67 9.15,13.6 9.15,10.65 9.22,10.38 9.31,10.26 9.86,9.72 9.99,9.63 10.14,9.6 10.9,9.6 10.92,9.6 11.22,9.49 11.35,9.2 11.35,7.9 11.2,7.59 10.88,7.51 10.79,7.51 10.68,7.5
5V_B on BOTTOM: 9.65,7.5 9.37,7.62 9.25,7.9 9.25,10.4 9.28,10.55 9.37,10.68 10.96,12.27 10.99,12.29 11.03,12.3 11.4,12.3 11.53,12.27 11.62,12.18 11.65,12.05 11.65,7.75 11.62,7.62 11.53,7.53 11.4,7.5
5V_B on CONDUCTIVE3: outline of 89 points within 2,3.4 15.25,31.85 ; 7 cut-outs
GND on TOP: outline of 582 points within 2,2 98,66 ; 18 cut-outs
GND on TOP: outline of 144 points within 2,31.67 11.7,54.43
GND on TOP: 2.25,58.6 2.12,58.63 2.03,58.73 2,58.85 2,62.21 2.04,62.29 2.12,62.31 5.05,63.11 6.25,65.9 6.27,65.97 6.35,66 15.6,66 15.67,65.97 15.7,65.9 15.7,60.95 15.66,60.81 15.54,60.72 15.5,60.71 11.74,60.71 11.69,60.7 8.05,60.7 7.92,60.67 7.83,60.58 7.8,60.45 7.8,59.6 7.78,59.51 7.74,59.43 7.7,59.41 7.66,59.4 6.4,59.4 6.31,59.39 6.2,59.35 6.18,59.35 3.8,59.35 3.66,59.29 3.6,59.15 3.6,58.7 3.57,58.63 3.5,58.6
GND on BOTTOM: outline of 674 points within 2,2 98,66 ; 16 cut-outs
GND on BOTTOM: 6.35,2 6.28,2.03 6.25,2.1 6.25,2.18 6.25,2.25 5.22,4.72 2.75,5.75 2.43,5.74 2.12,5.69 2.04,5.71 2,5.79 2,15.46 2.01,15.5 2.03,15.53 2.31,15.81 2.37,15.85 2.49,15.89 3.3,15.89 3.33,15.88 3.37,15.86 7.52,11.71 7.54,11.67 7.55,11.63 7.55,6.75 7.57,6.64 7.64,6.54 9.44,4.74 9.54,4.67 9.65,4.65 12.27,4.65 12.36,4.59 12.34,4.48 12.85,3.3 13.36,4.48 13.34,4.59 13.43,4.65 24.92,4.65 24.99,4.64 25.1,4.58 27.14,2.54 27.24,2.47 27.35,2.45 30.2,2.45 30.31,2.47 30.41,2.54 30.84,2.97 30.88,2.99 30.92,3 33.23,3 33.27,2.99 33.3,2.97 33.58,2.69 33.61,2.66 33.61,2.62 33.61,2.37 33.6,2.3 33.54,2.19 33.38,2.03 33.35,2.01 33.31,2
GND on CONDUCTIVE2: outline of 142 points within 2,2 98,66 ; 50 cut-outs
GND on CONDUCTIVE3: outline of 166 points within 39.66,2 91.27,16.9 ; 1 cut-out
GND on CONDUCTIVE3: outline of 98 points within 2,29.65 15.7,66 ; 3 cut-outs
GND on CONDUCTIVE3: 6.4,2 6.29,2.05 6.25,2.15 6.25,2.25 6.22,2.72 6.12,3.19 4.63,5.2 2.17,5.7 2.05,5.74 2,5.85 2,12.85 2.06,13.02 2.22,13.1 2.25,13.1 3,13.1 3.11,13.06 3.15,12.95 3.15,12.52 3.21,12.24 3.37,11.99 5.13,10.24 5.16,10.2 5.29,9.99 5.27,9.75 5.24,9.38 5.42,9.05 6.38,8.08 11.35,3.12 11.59,2.96 11.88,2.9 14.1,2.9 14.38,2.96 14.63,3.12 15.23,3.73 15.29,3.8 15.34,3.87 15.4,3.93 15.47,3.95 23.75,3.95 24.06,4.01 24.32,4.18 25.14,5.01 25.19,5.04 25.24,5.05 30.91,5.05 30.96,5.04 31.01,5.01 31.18,4.84 33.22,2.8 33.25,2.75 33.27,2.69 33.27,2.25 33.19,2.07 33.02,2
GND on CONDUCTIVE3: 15.83,5.55 15.74,5.57 15.69,5.64 15.62,5.77 14.87,6.53 14.84,6.58 14.83,6.64 14.83,7.72 14.84,7.79 14.9,7.9 15.31,8.3 15.35,8.33 15.41,8.35 16.56,8.35 16.67,8.29 16.71,8.17 17.2,7.6 17.69,8.17 17.73,8.29 17.84,8.35 22.33,8.35 22.39,8.33 22.44,8.3 22.72,8.02 23.06,7.83 23.25,7.8 29.8,7.8 30.17,7.9 30.33,8.02 32.51,10.21 32.56,10.24 32.62,10.25 38.85,10.25 38.96,10.21 39,10.1 39,8.7 38.96,8.59 38.85,8.55 38.55,8.55 38.46,8.53 38.38,8.48 38.28,8.44 38.18,8.49 34.7,9.02 32.96,5.96 32.92,5.85 32.81,5.8 32.54,5.8 32.49,5.81 32.44,5.84 31.87,6.42 31.61,6.59 31.3,6.65 24.85,6.65 24.54,6.59 24.28,6.42 23.46,5.59 23.41,5.56 23.36,5.55
GND on CONDUCTIVE3: 3.25,22.75 4.05,22.75
GND on CONDUCTIVE3: outline of 212 points within 10.3,2 98,66 ; 1 cut-out
VDD on TOP: 3.81,42.5 3.71,42.54 3.49,42.76 3.45,42.86 3.45,47.14 3.47,47.19 3.72,47.4 3.8,47.65 3.8,48.4 3.81,48.46 3.87,48.57 4.57,49.27 4.6,49.3 4.86,49.56 4.9,49.66 4.9,49.95 4.94,50.06 5.05,50.1 5.55,50.1 5.66,50.06 5.7,49.95 5.7,48.76 5.66,48.66 5.39,48.39 5.35,48.29 5.35,44.81 5.39,44.71 6.01,44.09 6.05,43.99 6.05,42.65 6.01,42.54 5.9,42.5
VDD on TOP: 8.55,15.25 8.48,15.28 8.45,15.35 8.45,16 8.36,16.21 8.15,16.3 7.55,16.3 7.48,16.33 7.45,16.4 7.45,16.49 7.48,16.56 7.55,16.59 7.59,16.59 8.39,16.59 8.53,16.65 8.59,16.79 8.59,17.71 8.53,17.85 8.39,17.91 7.02,17.91 7,17.92 6.9,17.95 6.81,17.96 6.52,17.96 6.48,17.97 6.45,17.99 6.32,18.12 6.3,18.15 6.29,18.19 6.29,19.92 6.29,19.94 6.42,20.2 6.69,20.3 8.63,20.3 8.67,20.29 8.71,20.27 9.12,19.86 9.14,19.82 9.15,19.78 9.15,15.35 9.12,15.28 9.05,15.25
VDD on TOP: 87.67,54.2 87.56,54.24 87.52,54.35 87.52,55.54 87.56,55.64 87.83,55.91 87.87,56.01 87.87,59.35 87.9,59.42 87.97,59.45 90.6,59.45 90.66,59.44 90.77,59.38 90.82,59.32 90.85,59.2 90.85,57.33 90.84,57.27 90.78,57.16 88.65,55.03 88.62,55 88.36,54.74 88.32,54.64 88.32,54.35 88.28,54.24 88.17,54.2
VDD on TOP: 92.7,13 92.63,13.03 92.6,13.1 92.6,13.9 92.51,14.11 92.3,14.2 91.7,14.2 91.63,14.23 91.6,14.3 91.6,14.39 91.63,14.46 91.7,14.49 92.54,14.49 92.64,14.51 92.71,14.59 92.74,14.69 92.74,15.61 92.71,15.71 92.64,15.79 92.54,15.81 91.17,15.81 91.15,15.82 91.05,15.85 90.96,15.86 90.46,15.86 90.39,15.89 90.36,15.96 90.36,18.05 90.37,18.09 90.39,18.12 90.75,18.47 90.78,18.49 90.82,18.5 93.11,18.5 93.15,18.49 93.18,18.47 93.73,17.92 93.77,17.87 93.8,17.75 93.8,13.1 93.77,13.03 93.7,13
VDD on TOP: 27.9,5.7 27.72,5.77 27.65,5.95 27.65,10.3 27.72,10.48 27.9,10.55 30.1,10.55 30.28,10.48 30.35,10.3 30.35,5.95 30.28,5.77 30.1,5.7
VDD on BOTTOM: 43.25,7.26 43.22,7.27 43.18,7.29 42.03,8.45 42.01,8.48 42,8.52 42,8.55 41.94,8.69 41.8,8.75 40.21,8.75 40.18,8.75 40.08,8.79 40,8.8 39.8,8.8 39.76,8.81 39.73,8.83 39.3,9.25 39.25,9.3 39.2,9.33 38.9,9.5 38.22,9.52 37.85,8.94 37.8,8.85 37.7,8.86 36.83,9.23 35.9,9.33 34.65,8.99 33.64,8.18 33.38,7.81 33.18,7.41 33.15,7.37 33.09,7.35 27.95,7.35 27.82,7.38 27.73,7.47 27.7,7.6 27.7,11.7 27.71,11.76 27.77,11.87 28.73,12.83 28.78,12.87 28.9,12.9 43.81,12.9 43.85,12.89 43.88,12.87 45.38,11.37 45.42,11.32 45.45,11.2 45.45,8.87 45.42,8.8 45.35,8.77 44.92,8.77 44.17,8.43 43.93,7.65 43.93,7.51 43.89,7.39 43.8,7.3 43.68,7.26
VDD on BOTTOM: 4.44,42.55 4.4,42.56 4.37,42.58 4.22,42.73 4.18,42.78 4.15,42.9 4.15,45.55 4.18,45.62 4.25,45.65 4.6,45.65 4.74,45.71 4.8,45.85 4.8,48.53 4.81,48.57 4.83,48.6 5.58,49.35 5.63,49.39 5.75,49.42 7.7,49.42 7.82,49.46 7.87,49.5 8.81,50.44 8.87,50.48 8.99,50.51 9.43,50.51 9.5,50.48 9.53,50.41 9.53,46.37 9.52,46.33 9.5,46.3 9.28,46.08 9.25,46.06 9.21,46.05 7.05,46.05 6.93,46.02 6.88,45.98 6.15,45.25 6.15,42.8 6.12,42.67 6.02,42.58 5.9,42.55
VDD on BOTTOM: 83.95,54.5 83.83,54.53 83.73,54.62 83.7,54.75 83.7,59.15 83.73,59.27 83.83,59.37 83.95,59.4 90.56,59.4 90.6,59.39 90.63,59.37 90.88,59.12 90.93,59.04 90.95,58.95 90.95,58 90.93,57.91 90.88,57.83 90.58,57.53 90.55,57.51 90.51,57.5 89.95,57.5 89.86,57.48 89.78,57.43 88.23,55.88 88.18,55.8 88.16,55.71 88.16,55.2 88.14,55.13 88.07,55.1 88.05,55.1 85.4,55.1 84.87,54.57 84.82,54.53 84.7,54.5
VDD on CONDUCTIVE3: outline of 246 points within 3.7,8.3 94.1,59.95 ; 14 cut-outs
VEE_A on TOP: 55.35,54.3 55.28,54.33 55.25,54.4 55.25,62.61 55.26,62.65 55.28,62.68 55.67,63.07 55.7,63.09 55.74,63.1 57.25,63.1 57.36,63.06 57.4,62.95 57.4,61.41 57.44,61.31 57.66,61.09 57.7,60.99 57.7,58.66 57.74,58.56 58.26,58.04 58.3,57.94 58.3,54.45 58.26,54.34 58.15,54.3
VEE_A on BOTTOM: 56.41,53.4 56.31,53.44 55.53,54.22 55.51,54.25 55.5,54.29 55.5,57.05 55.54,57.16 55.65,57.2 58.25,57.2 58.36,57.16 58.4,57.05 58.4,53.55 58.36,53.44 58.25,53.4
VEE_A on CONDUCTIVE3: outline of 113 points within 55.4,31.35 65.4,56.6 ; 4 cut-outs
VEE_B on TOP: 36.5,43.2 36.38,43.23 36.28,43.33 36.25,43.45 36.25,46.15 36.22,46.27 36.18,46.32 35.61,46.89 35.6,46.94 35.6,48.7 35.63,48.83 35.73,48.92 35.85,48.95 38.8,48.95 38.92,48.92 39.02,48.83 39.05,48.7 39.05,43.45 39.02,43.33 38.92,43.23 38.8,43.2
VEE_B on BOTTOM: 37.05,43.15 36.92,43.18 36.83,43.27 36.8,43.4 36.8,49.3 36.83,49.42 36.92,49.52 37.05,49.55 38.8,49.55 38.87,49.52 38.9,49.45 38.9,43.4 38.87,43.27 38.77,43.18 38.65,43.15
VEE_B on CONDUCTIVE3: 36.23,33.96 35.43,34.98 34.3,34.36 34.24,34.29 34.16,34.26 33.1,34.26 32.98,34.29 32.88,34.38 32.85,34.51 32.85,40.36 32.86,40.43 32.92,40.54 36.66,44.27 36.85,44.61 36.88,44.8 36.88,47.94 36.89,48.04 37.71,48.88 37.75,48.91 37.81,48.92 38.79,48.92 38.85,48.91 38.89,48.88 39.48,48.29 39.52,48.24 39.55,48.12 39.55,33.96 39.55,33.93 39.54,33.89 39.49,33.81 39.4,33.78 38.92,33.78 38.81,33.83 38.77,33.94 37.8,35 36.77,34 36.77,33.95 36.73,33.84 36.62,33.8 36.38,33.8 36.27,33.84 ; 5 cut-outs
SIG00042 on TOP: 61.35,44.6 61.23,44.63 61.13,44.73 61.1,44.85 61.1,46.85 61.07,46.97 61.03,47.02 60.69,47.36 60.65,47.41 60.62,47.53 60.62,49.05 60.65,49.12 60.72,49.15 64.07,49.15 64.19,49.12 64.29,49.02 64.32,48.9 64.32,48.29 64.7,47.37 65.62,46.99 66.25,46.99 66.38,46.96 66.47,46.87 66.5,46.74 66.5,44.78 66.5,44.75 66.49,44.73 66.4,44.63 66.27,44.6
SIG00044 on TOP: 54.42,44.05 54.3,44.08 54.2,44.17 54.17,44.3 54.17,51 54.2,51.12 54.3,51.22 54.42,51.25 56.25,51.25 56.38,51.22 56.47,51.12 56.5,51 56.5,49.95 56.53,49.83 56.62,49.73 56.75,49.7 59.41,49.7 59.45,49.69 59.48,49.67 59.92,49.23 59.94,49.2 59.95,49.16 59.95,47.84 59.94,47.8 59.92,47.77 59.43,47.28 59.4,47.26 59.36,47.25 57.3,47.25 57.18,47.22 57.13,47.18 57.07,47.12 57.01,47.01 57,46.95 57,44.3 56.97,44.17 56.88,44.08 56.75,44.05
SIG00044 on BOTTOM: 54.05,43.6 53.98,43.63 53.95,43.7 53.95,49.55 53.98,49.62 54.05,49.65 56.4,49.65 56.52,49.62 56.62,49.52 56.65,49.4 56.65,43.85 56.62,43.73 56.52,43.63 56.4,43.6
SIG00044 on CONDUCTIVE3: 51.59,28.08 51.55,28.19 51.55,48 51.57,48.09 51.62,48.17 52.76,49.31 52.8,49.34 52.86,49.35 54.69,49.35 54.75,49.34 54.79,49.31 55.31,48.79 55.34,48.75 55.35,48.69 55.35,40.23 55.31,40.12 54.51,39.78 54.23,39.08 54.23,31.46 54.52,30.75 55.23,30.46 59.4,30.46 59.58,30.39 59.65,30.21 59.65,28.12 59.64,28.06 59.61,28.01 58.94,27.34 58.89,27.31 58.83,27.3 52.44,27.3 52.38,27.31 52.33,27.34 ; 3 cut-outs
SIG00050 on TOP: 63.4,55.8 63.34,55.81 63.23,55.87 62.63,56.47 62.61,56.5 62.6,56.54 62.6,58.05 62.57,58.17 62.53,58.22 62.09,58.66 62.05,58.69 61.99,58.7 60.85,58.7 60.78,58.73 60.75,58.8 60.75,60.76 60.76,60.8 60.78,60.83 61.46,61.51 61.49,61.55 61.5,61.61 61.5,62.7 61.53,62.77 61.6,62.8 63.49,62.8 63.55,62.79 63.59,62.76 66.03,60.32 66.07,60.27 66.1,60.15 66.1,57.84 66.07,57.72 65.97,57.62 65.85,57.59 65.62,57.59 64.7,57.21 64.32,56.29 64.32,56.05 64.29,55.92 64.19,55.83 64.07,55.8
SIG00058 on TOP: 83.95,45.1 83.83,45.13 83.73,45.23 83.7,45.35 83.7,50.6 83.73,50.67 83.8,50.7 84.65,50.7 84.69,50.69 84.73,50.67 85.71,49.69 85.84,49.6 85.99,49.57 86.82,49.57 86.94,49.54 87.04,49.45 87.07,49.32 87.07,45.35 87.04,45.23 86.94,45.13 86.82,45.1
SIG00058 on BOTTOM: 83.93,45.1 83.8,45.13 83.71,45.23 83.68,45.35 83.68,50.1 83.67,50.11 83.67,50.3 83.71,50.42 83.8,50.52 83.92,50.55 84.45,50.55 84.51,50.54 84.63,50.48 85.35,49.75 86.35,49.75 86.44,49.73 86.52,49.68 86.88,49.32 86.93,49.24 86.95,49.15 86.95,47.7 87.02,47.52 87.2,47.45 88.3,47.45 88.48,47.38 88.55,47.2 88.55,45.35 88.52,45.23 88.42,45.13 88.3,45.1
